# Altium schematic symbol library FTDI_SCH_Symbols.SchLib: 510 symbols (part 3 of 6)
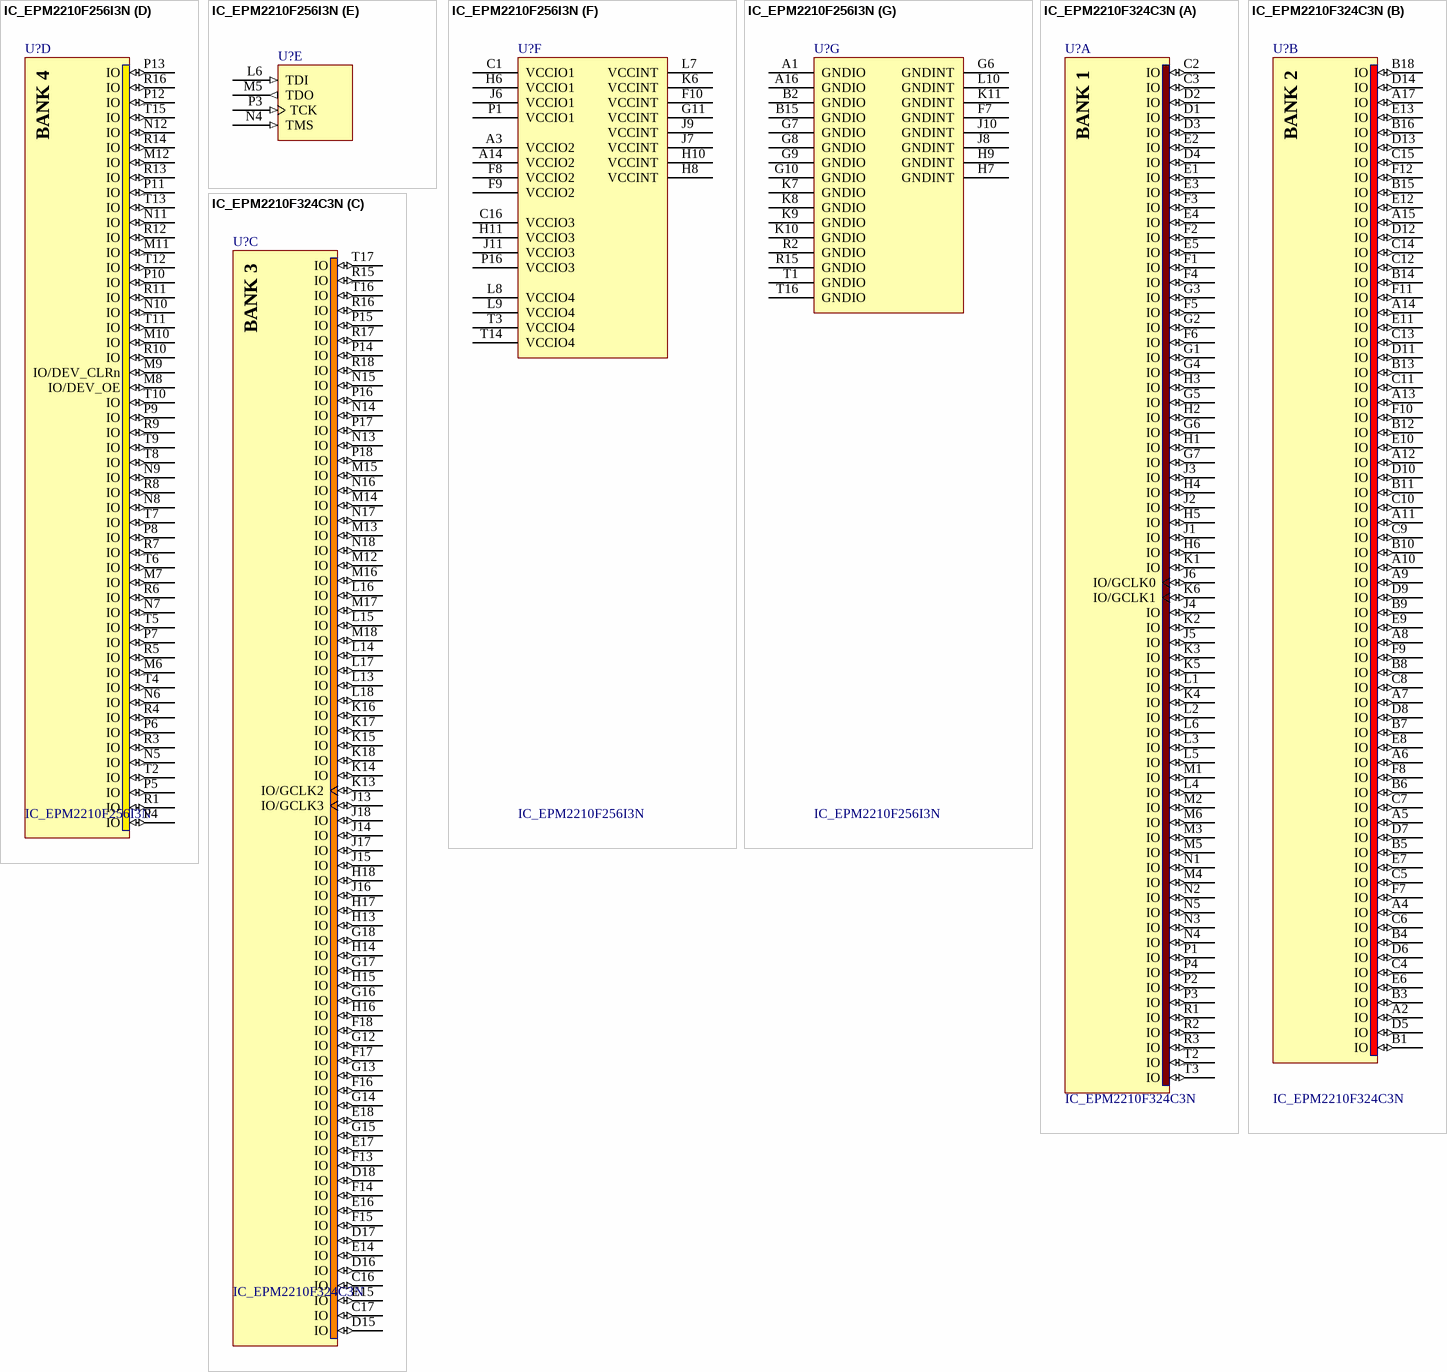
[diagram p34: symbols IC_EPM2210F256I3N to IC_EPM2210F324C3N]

## IC_EPM2210F256I3N
designator U?
MAX II 3.3/2.5V CPLD, 204 IOs, 2,210 Logic Elements, 256-Pin FineLine BGA, Industrial Temperature, Speed Grade 3, Pb-Free; Note: Each set of VCCIO pins can be connected to 3.3V, 2.5V, 1.8V, or 1.5V.; Note: All VCCINT pins must be connected to either 3.3V or 2.5V (but not a combination of both).
footprint FBGA256 (BGA, 256-Leads, Body 17x17mm, Pitch 1mm)
3D model EPM2210-FBGA256 (256-Ball FineLine Ball Grid Array (FBGA256) - Option 1)
part A pins: C2 IO (io), C3 IO (io), D1 IO (io), D2 IO (io), D3 IO (io), E1 IO (io), E2 IO (io), E3 IO (io), E4 IO (io), E5 IO (io), F1 IO (io), F2 IO (io), F3 IO (io), F4 IO (io), F5 IO (io), F6 IO (io), G1 IO (io), G2 IO (io), G3 IO (io), G4 IO (io), G5 IO (io), H1 IO (io), H2 IO (io), H3 IO (io), H4 IO (io), H5 IO/GCLK0 (io), J1 IO (io), J2 IO (io), J3 IO (io), J4 IO (io), J5 IO/GCLK1 (io), K1 IO (io), K2 IO (io), K3 IO (io), K4 IO (io), K5 IO (io), L1 IO (io), L2 IO (io), L3 IO (io), L4 IO (io), L5 IO (io), M1 IO (io), M2 IO (io), M3 IO (io), M4 IO (io), N1 IO (io), N2 IO (io), N3 IO (io), P2 IO (io)
part B pins: A2 IO (io), A4 IO (io), A5 IO (io), A6 IO (io), A7 IO (io), A8 IO (io), A9 IO (io), A10 IO (io), A11 IO (io), A12 IO (io), A13 IO (io), A15 IO (io), B1 IO (io), B3 IO (io), B4 IO (io), B5 IO (io), B6 IO (io), B7 IO (io), B8 IO (io), B9 IO (io), B10 IO (io), B11 IO (io), B12 IO (io), B13 IO (io), B14 IO (io), B16 IO (io), C4 IO (io), C5 IO (io), C6 IO (io), C7 IO (io), C8 IO (io), C9 IO (io), C10 IO (io), C11 IO (io), C12 IO (io), C13 IO (io), D4 IO (io), D5 IO (io), D6 IO (io), D7 IO (io), D8 IO (io), D9 IO (io), D10 IO (io), D11 IO (io), D12 IO (io), E6 IO (io), E7 IO (io), E8 IO (io), E9 IO (io), E10 IO (io), E11 IO (io)
part C pins: C14 IO (io), C15 IO (io), D13 IO (io), D14 IO (io), D15 IO (io), D16 IO (io), E12 IO (io), E13 IO (io), E14 IO (io), E15 IO (io), E16 IO (io), F11 IO (io), F12 IO (io), F13 IO (io), F14 IO (io), F15 IO (io), F16 IO (io), G12 IO (io), G13 IO (io), G14 IO (io), G15 IO (io), G16 IO (io), H12 IO/GCLK3 (io), H13 IO (io), H14 IO (io), H15 IO (io), H16 IO (io), J12 IO/GCLK2 (io), J13 IO (io), J14 IO (io), J15 IO (io), J16 IO (io), K12 IO (io), K13 IO (io), K14 IO (io), K15 IO (io), K16 IO (io), L11 IO (io), L12 IO (io), L13 IO (io), L14 IO (io), L15 IO (io), L16 IO (io), M13 IO (io), M14 IO (io), M15 IO (io), M16 IO (io), N13 IO (io), N14 IO (io), N15 IO (io), N16 IO (io), P14 IO (io), P15 IO (io)
part D pins: M6 IO (io), M7 IO (io), M8 IO/DEV_OE (io), M9 IO/DEV_CLRn (io), M10 IO (io), M11 IO (io), M12 IO (io), N5 IO (io), N6 IO (io), N7 IO (io), N8 IO (io), N9 IO (io), N10 IO (io), N11 IO (io), N12 IO (io), P4 IO (io), P5 IO (io), P6 IO (io), P7 IO (io), P8 IO (io), P9 IO (io), P10 IO (io), P11 IO (io), P12 IO (io), P13 IO (io), R1 IO (io), R3 IO (io), R4 IO (io), R5 IO (io), R6 IO (io), R7 IO (io), R8 IO (io), R9 IO (io), R10 IO (io), R11 IO (io), R12 IO (io), R13 IO (io), R14 IO (io), R16 IO (io), T2 IO (io), T4 IO (io), T5 IO (io), T6 IO (io), T7 IO (io), T8 IO (io), T9 IO (io), T10 IO (io), T11 IO (io), T12 IO (io), T13 IO (io), T15 IO (io)
part E pins: L6 TDI (in), M5 TDO (out), N4 TMS (in), P3 TCK (in)
part F pins: A3 VCCIO2 (power), A14 VCCIO2 (power), C1 VCCIO1 (power), C16 VCCIO3 (power), F8 VCCIO2 (power), F9 VCCIO2 (power), F10 VCCINT (power), G11 VCCINT (power), H6 VCCIO1 (power), H8 VCCINT (power), H10 VCCINT (power), H11 VCCIO3 (power), J6 VCCIO1 (power), J7 VCCINT (power), J9 VCCINT (power), J11 VCCIO3 (power), K6 VCCINT (power), L7 VCCINT (power), L8 VCCIO4 (power), L9 VCCIO4 (power), P1 VCCIO1 (power), P16 VCCIO3 (power), T3 VCCIO4 (power), T14 VCCIO4 (power)
part G pins: A1 GNDIO (power), A16 GNDIO (power), B2 GNDIO (power), B15 GNDIO (power), F7 GNDINT (power), G6 GNDINT (power), G7 GNDIO (power), G8 GNDIO (power), G9 GNDIO (power), G10 GNDIO (power), H7 GNDINT (power), H9 GNDINT (power), J8 GNDINT (power), J10 GNDINT (power), K7 GNDIO (power), K8 GNDIO (power), K9 GNDIO (power), K10 GNDIO (power), K11 GNDINT (power), L10 GNDINT (power), R2 GNDIO (power), R15 GNDIO (power), T1 GNDIO (power), T16 GNDIO (power)

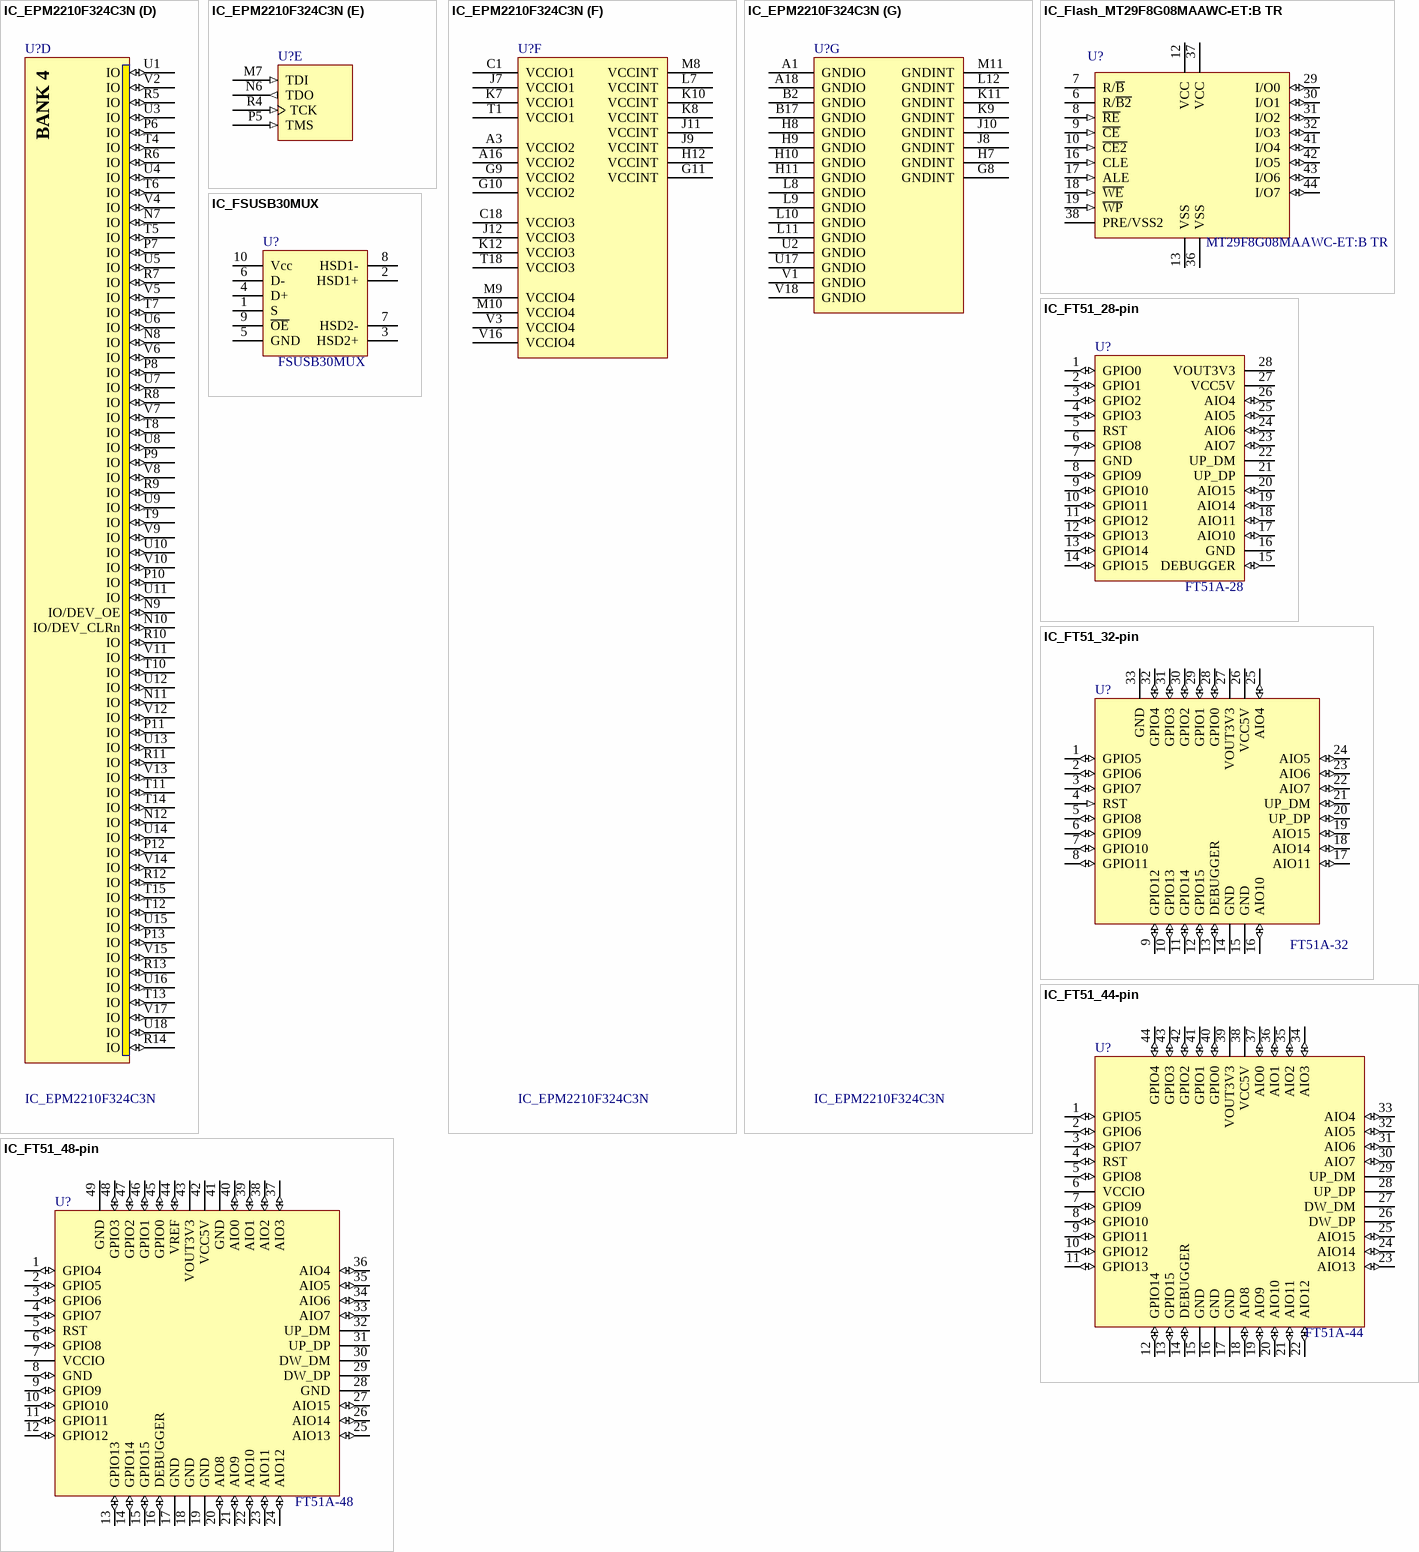
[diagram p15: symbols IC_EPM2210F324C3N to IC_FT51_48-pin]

## IC_EPM2210F324C3N
designator U?
MAX II 3.3/2.5V CPLD, 272 IOs, 2,210 Logic Elements, 324-Pin FineLine BGA, Commercial Temperature, Speed Grade 3, Pb-Free; Note: Each set of VCCIO pins can be connected to 3.3V, 2.5V, 1.8V, or 1.5V.; Note: All VCCINT pins must be connected to either 3.3V or 2.5V (but not a combination of both).
footprint FBGA324 (BGA, 324-Leads, Body 19x19mm, Pitch 1mm)
3D model EPM2210-FBGA324 (324-Ball FineLine Ball Grid Array (FBGA324))
part A pins: C2 IO (io), C3 IO (io), D1 IO (io), D2 IO (io), D3 IO (io), D4 IO (io), E1 IO (io), E2 IO (io), E3 IO (io), E4 IO (io), E5 IO (io), F1 IO (io), F2 IO (io), F3 IO (io), F4 IO (io), F5 IO (io), F6 IO (io), G1 IO (io), G2 IO (io), G3 IO (io), G4 IO (io), G5 IO (io), G6 IO (io), G7 IO (io), H1 IO (io), H2 IO (io), H3 IO (io), H4 IO (io), H5 IO (io), H6 IO (io), J1 IO (io), J2 IO (io), J3 IO (io), J4 IO (io), J5 IO (io), J6 IO/GCLK0 (io), K1 IO (io), K2 IO (io), K3 IO (io), K4 IO (io), K5 IO (io), K6 IO/GCLK1 (io), L1 IO (io), L2 IO (io), L3 IO (io), L4 IO (io), L5 IO (io), L6 IO (io), M1 IO (io), M2 IO (io), M3 IO (io), M4 IO (io), M5 IO (io), M6 IO (io), N1 IO (io), N2 IO (io), N3 IO (io), N4 IO (io), N5 IO (io), P1 IO (io), P2 IO (io), P3 IO (io), P4 IO (io), R1 IO (io), R2 IO (io), R3 IO (io), T2 IO (io), T3 IO (io)
part B pins: A2 IO (io), A4 IO (io), A5 IO (io), A6 IO (io), A7 IO (io), A8 IO (io), A9 IO (io), A10 IO (io), A11 IO (io), A12 IO (io), A13 IO (io), A14 IO (io), A15 IO (io), A17 IO (io), B1 IO (io), B3 IO (io), B4 IO (io), B5 IO (io), B6 IO (io), B7 IO (io), B8 IO (io), B9 IO (io), B10 IO (io), B11 IO (io), B12 IO (io), B13 IO (io), B14 IO (io), B15 IO (io), B16 IO (io), B18 IO (io), C4 IO (io), C5 IO (io), C6 IO (io), C7 IO (io), C8 IO (io), C9 IO (io), C10 IO (io), C11 IO (io), C12 IO (io), C13 IO (io), C14 IO (io), C15 IO (io), D5 IO (io), D6 IO (io), D7 IO (io), D8 IO (io), D9 IO (io), D10 IO (io), D11 IO (io), D12 IO (io), D13 IO (io), D14 IO (io), E6 IO (io), E7 IO (io), E8 IO (io), E9 IO (io), E10 IO (io), E11 IO (io), E12 IO (io), E13 IO (io), F7 IO (io), F8 IO (io), F9 IO (io), F10 IO (io), F11 IO (io), F12 IO (io)
part C pins: C16 IO (io), C17 IO (io), D15 IO (io), D16 IO (io), D17 IO (io), D18 IO (io), E14 IO (io), E15 IO (io), E16 IO (io), E17 IO (io), E18 IO (io), F13 IO (io), F14 IO (io), F15 IO (io), F16 IO (io), F17 IO (io), F18 IO (io), G12 IO (io), G13 IO (io), G14 IO (io), G15 IO (io), G16 IO (io), G17 IO (io), G18 IO (io), H13 IO (io), H14 IO (io), H15 IO (io), H16 IO (io), H17 IO (io), H18 IO (io), J13 IO/GCLK3 (io), J14 IO (io), J15 IO (io), J16 IO (io), J17 IO (io), J18 IO (io), K13 IO/GCLK2 (io), K14 IO (io), K15 IO (io), K16 IO (io), K17 IO (io), K18 IO (io), L13 IO (io), L14 IO (io), L15 IO (io), L16 IO (io), L17 IO (io), L18 IO (io), M12 IO (io), M13 IO (io), M14 IO (io), M15 IO (io), M16 IO (io), M17 IO (io), M18 IO (io), N13 IO (io), N14 IO (io), N15 IO (io), N16 IO (io), N17 IO (io), N18 IO (io), P14 IO (io), P15 IO (io), P16 IO (io), P17 IO (io), P18 IO (io), R15 IO (io), R16 IO (io), R17 IO (io), R18 IO (io), T16 IO (io), T17 IO (io)
part D pins: N7 IO (io), N8 IO (io), N9 IO/DEV_OE (io), N10 IO/DEV_CLRn (io), N11 IO (io), N12 IO (io), P6 IO (io), P7 IO (io), P8 IO (io), P9 IO (io), P10 IO (io), P11 IO (io), P12 IO (io), P13 IO (io), R5 IO (io), R6 IO (io), R7 IO (io), R8 IO (io), R9 IO (io), R10 IO (io), R11 IO (io), R12 IO (io), R13 IO (io), R14 IO (io), T4 IO (io), T5 IO (io), T6 IO (io), T7 IO (io), T8 IO (io), T9 IO (io), T10 IO (io), T11 IO (io), T12 IO (io), T13 IO (io), T14 IO (io), T15 IO (io), U1 IO (io), U3 IO (io), U4 IO (io), U5 IO (io), U6 IO (io), U7 IO (io), U8 IO (io), U9 IO (io), U10 IO (io), U11 IO (io), U12 IO (io), U13 IO (io), U14 IO (io), U15 IO (io), U16 IO (io), U18 IO (io), V2 IO (io), V4 IO (io), V5 IO (io), V6 IO (io), V7 IO (io), V8 IO (io), V9 IO (io), V10 IO (io), V11 IO (io), V12 IO (io), V13 IO (io), V14 IO (io), V15 IO (io), V17 IO (io)
part E pins: M7 TDI (in), N6 TDO (out), P5 TMS (in), R4 TCK (in)
part F pins: A3 VCCIO2 (power), A16 VCCIO2 (power), C1 VCCIO1 (power), C18 VCCIO3 (power), G9 VCCIO2 (power), G10 VCCIO2 (power), G11 VCCINT (power), H12 VCCINT (power), J7 VCCIO1 (power), J9 VCCINT (power), J11 VCCINT (power), J12 VCCIO3 (power), K7 VCCIO1 (power), K8 VCCINT (power), K10 VCCINT (power), K12 VCCIO3 (power), L7 VCCINT (power), M8 VCCINT (power), M9 VCCIO4 (power), M10 VCCIO4 (power), T1 VCCIO1 (power), T18 VCCIO3 (power), V3 VCCIO4 (power), V16 VCCIO4 (power)
part G pins: A1 GNDIO (power), A18 GNDIO (power), B2 GNDIO (power), B17 GNDIO (power), G8 GNDINT (power), H7 GNDINT (power), H8 GNDIO (power), H9 GNDIO (power), H10 GNDIO (power), H11 GNDIO (power), J8 GNDINT (power), J10 GNDINT (power), K9 GNDINT (power), K11 GNDINT (power), L8 GNDIO (power), L9 GNDIO (power), L10 GNDIO (power), L11 GNDIO (power), L12 GNDINT (power), M11 GNDINT (power), U2 GNDIO (power), U17 GNDIO (power), V1 GNDIO (power), V18 GNDIO (power)

## IC_Flash_MT29F8G08MAAWC-ET:B TR
designator U?, comment MT29F8G08MAAWC-ET:B TR
8Gb: x8 Multiplexed NAND Flash Memory
footprint TSOP_Type1_50P2000X120-48N (TSOP Type 1, 48-Leads, Body 12.1x18.5mm (max), Pitch 0.50mm, IPC Medium Density)
pins: 1 NC hidden, 2 NC hidden, 3 NC hidden, 4 NC hidden, 5 NC hidden, 6 R/~{B2} (oc), 7 R/~{B} (oc), 8 ~{RE} (in), 9 ~{CE} (in), 10 ~{CE2} (in), 11 NC hidden, 12 VCC (power), 13 VSS (power), 14 NC hidden, 15 NC hidden, 16 CLE (in), 17 ALE (in), 18 ~{WE} (in), 19 ~{WP} (in), 20 DNU hidden, 21 DNU hidden, 22 DNU hidden, 23 NC hidden, 24 NC hidden, 25 NC hidden, 26 NC hidden, 27 NC hidden, 28 NC hidden, 29 I/O0 (io), 30 I/O1 (io), 31 I/O2 (io), 32 I/O3 (io), 33 NC hidden, 34 NC hidden, 35 NC hidden, 36 VSS (power), 37 VCC (power), 38 PRE/VSS2 (power), 39 NC hidden, 40 NC hidden, 41 I/O4 (io), 42 I/O5 (io), 43 I/O6 (io), 44 I/O7 (io), 45 NC hidden, 46 NC hidden, 47 NC hidden, 48 NC hidden

## IC_FSUSB30MUX
designator U?, comment FSUSB30MUX
Low Power, Two Port, High Speed USB2.0 Switch
footprint MSOP50P490X120-10N (MSOP, 10-Leads, Body 3.1x3.1mm (max), Pitch 0.50mm, IPC Medium Density)
pins: 1 S, 2 HSD1+, 3 HSD2+, 4 D+, 5 GND, 6 D-, 7 HSD2-, 8 HSD1-, 9 ~{OE}, 10 Vcc

## IC_FT51_28-pin
designator U?, comment FT51A-28
Preliminary symbol - DO NOT USE FOR COMERCIAL DESIGNS
pins: 1 GPIO0 (io), 2 GPIO1 (io), 3 GPIO2 (io), 4 GPIO3 (io), 5 RST (power), 6 GPIO8 (io), 7 GND (power), 8 GPIO9 (io), 9 GPIO10 (io), 10 GPIO11 (io), 11 GPIO12 (io), 12 GPIO13 (io), 13 GPIO14 (io), 14 GPIO15 (io), 15 DEBUGGER (io), 16 GND (power), 17 AIO10 (io), 18 AIO11 (io), 19 AIO14 (io), 20 AIO15 (io), 21 UP_DP, 22 UP_DM, 23 AIO7 (io), 24 AIO6 (io), 25 AIO5 (io), 26 AIO4 (io), 27 VCC5V (power), 28 VOUT3V3 (power)

## IC_FT51_32-pin
designator U?, comment FT51A-32
FT51A 32 pin QFN
footprint QFN50P598X598X75-32N (QFN, 32-Leads, Body 6.0x6.0mm (max), Pitch 0.50mm, IPC Medium Density)
pins: 1 GPIO5 (io), 2 GPIO6 (io), 3 GPIO7 (io), 4 RST (in), 5 GPIO8 (io), 6 GPIO9 (io), 7 GPIO10 (io), 8 GPIO11 (io), 9 GPIO12 (io), 10 GPIO13 (io), 11 GPIO14 (io), 12 GPIO15 (io), 13 DEBUGGER (io), 14 GND (power), 15 GND (power), 16 AIO10 (io), 17 AIO11 (io), 18 AIO14 (io), 19 AIO15 (io), 20 UP_DP (io), 21 UP_DM (io), 22 AIO7 (io), 23 AIO6 (io), 24 AIO5 (io), 25 AIO4 (io), 26 VCC5V (power), 27 VOUT3V3 (power), 28 GPIO0 (io), 29 GPIO1 (io), 30 GPIO2 (io), 31 GPIO3 (io), 32 GPIO4 (io), 33 GND

## IC_FT51_44-pin
designator U?, comment FT51A-44
Preliminary symbol - DO NOT USE FOR COMERCIAL DESIGNS
pins: 1 GPIO5 (io), 2 GPIO6 (io), 3 GPIO7 (io), 4 RST (io), 5 GPIO8 (io), 6 VCCIO (power), 7 GPIO9 (io), 8 GPIO10 (io), 9 GPIO11 (io), 10 GPIO12 (io), 11 GPIO13 (io), 12 GPIO14 (io), 13 GPIO15 (io), 14 DEBUGGER (io), 15 GND (power), 16 GND (power), 17 GND (power), 18 AIO8 (io), 19 AIO9 (io), 20 AIO10 (io), 21 AIO11 (io), 22 AIO12 (io), 23 AIO13 (io), 24 AIO14 (io), 25 AIO15 (io), 26 DW_DP, 27 DW_DM, 28 UP_DP, 29 UP_DM, 30 AIO7 (io), 31 AIO6 (io), 32 AIO5 (io), 33 AIO4 (io), 34 AIO3 (io), 35 AIO2 (io), 36 AIO1 (io), 37 AIO0 (io), 38 VCC5V (power), 39 VOUT3V3 (power), 40 GPIO0 (io), 41 GPIO1 (io), 42 GPIO2 (io), 43 GPIO3 (io), 44 GPIO4 (io)

## IC_FT51_48-pin
designator U?, comment FT51A-48
Preliminary symbol - DO NOT USE FOR COMERCIAL DESIGNS
pins: 1 GPIO4 (io), 2 GPIO5 (io), 3 GPIO6 (io), 4 GPIO7 (io), 5 RST (io), 6 GPIO8 (io), 7 VCCIO (power), 8 GND (io), 9 GPIO9 (io), 10 GPIO10 (io), 11 GPIO11 (io), 12 GPIO12 (io), 13 GPIO13 (io), 14 GPIO14 (io), 15 GPIO15 (io), 16 DEBUGGER (io), 17 GND (power), 18 GND (power), 19 GND (power), 20 AIO8 (io), 21 AIO9 (io), 22 AIO10 (io), 23 AIO11 (io), 24 AIO12 (io), 25 AIO13 (io), 26 AIO14 (io), 27 AIO15 (io), 28 GND (power), 29 DW_DP, 30 DW_DM, 31 UP_DP, 32 UP_DM, 33 AIO7 (io), 34 AIO6 (io), 35 AIO5 (io), 36 AIO4 (io), 37 AIO3 (io), 38 AIO2 (io), 39 AIO1 (io), 40 AIO0 (io), 41 GND (power), 42 VCC5V (power), 43 VOUT3V3 (power), 44 VREF (io), 45 GPIO0 (io), 46 GPIO1 (io), 47 GPIO2 (io), 48 GPIO3 (io), 49 GND (power)

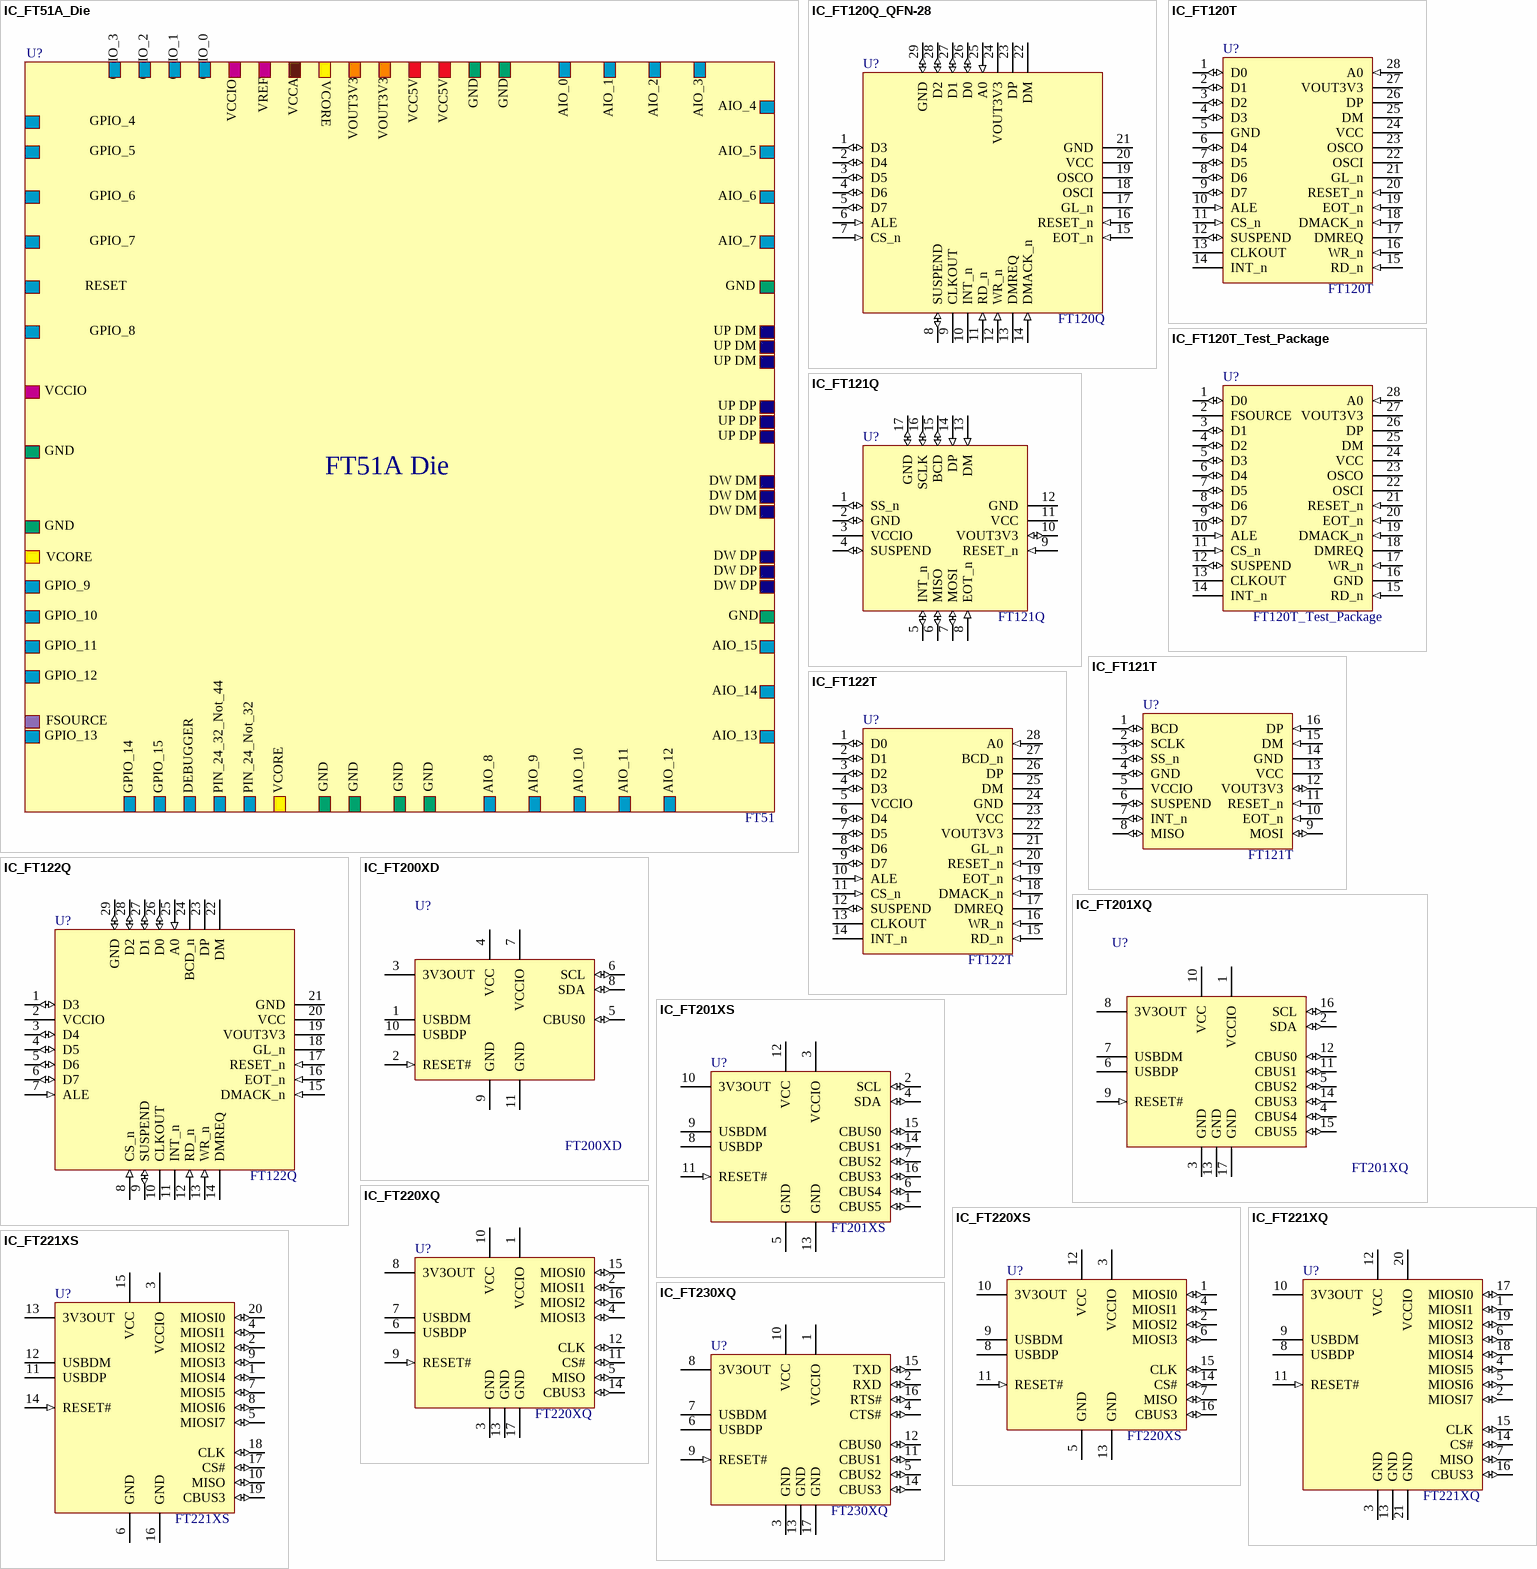
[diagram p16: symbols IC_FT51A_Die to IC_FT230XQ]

## IC_FT51A_Die
designator U?, comment FT51
Not for customer designs

## IC_FT120Q_QFN-28
designator U?, comment FT120Q
footprint QFN40P400X400X90-28N (QFN, 28-Leads, Body 4x4mm (max), Pitch 0.40mm, IPC Medium Density)
pins: 1 D3 (io), 2 D4 (io), 3 D5 (io), 4 D6 (io), 5 D7 (io), 6 ALE (in), 7 CS_n (in), 8 SUSPEND (io), 9 CLKOUT, 10 INT_n (oc), 11 RD_n (in), 12 WR_n (in), 13 DMREQ (oc), 14 DMACK_n (in), 15 EOT_n (in), 16 RESET_n (in), 17 GL_n (oc), 18 OSCI, 19 OSCO, 20 VCC (power), 21 GND (power), 22 DM, 23 DP, 24 VOUT3V3 (power), 25 A0 (in), 26 D0 (io), 27 D1 (io), 28 D2 (io), 29 GND (io)

## IC_FT120T
designator U?, comment FT120T
footprint TSSOP65P640X120-28N (TSSOP, 28-Leads, Body 9.8x4.4mm (max), Pitch 0.65mm, IPC Medium Density)
pins: 1 D0 (io), 2 D1 (io), 3 D2 (io), 4 D3 (io), 5 GND (power), 6 D4 (io), 7 D5 (io), 8 D6 (io), 9 D7 (io), 10 ALE (in), 11 CS_n (in), 12 SUSPEND (io), 13 CLKOUT, 14 INT_n (oc), 15 RD_n (in), 16 WR_n (in), 17 DMREQ (oc), 18 DMACK_n (in), 19 EOT_n (in), 20 RESET_n (in), 21 GL_n (oc), 22 OSCI, 23 OSCO, 24 VCC (power), 25 DM, 26 DP, 27 VOUT3V3 (power), 28 A0 (in)

## IC_FT120T_Test_Package
designator U?, comment FT120T_Test_Package
footprint TSSOP65P640X120-28N (TSSOP, 28-Leads, Body 9.8x4.4mm (max), Pitch 0.65mm, IPC Medium Density)
pins: 1 D0 (io), 2 FSOURCE (power), 3 D1 (io), 4 D2 (io), 5 D3 (io), 6 D4 (io), 7 D5 (io), 8 D6 (io), 9 D7 (io), 10 ALE (in), 11 CS_n (in), 12 SUSPEND (io), 13 CLKOUT, 14 INT_n (oc), 15 RD_n (in), 16 GND (oc), 17 WR_n (in), 18 DMREQ (oc), 19 DMACK_n (in), 20 EOT_n (in), 21 RESET_n (in), 22 OSCI, 23 OSCO, 24 VCC (power), 25 DM, 26 DP, 27 VOUT3V3 (power), 28 A0 (in)

## IC_FT121Q
designator U?, comment FT121Q
footprint QFN50P300X300X90-16N (QFN, 16-Leads, Body 3.1x3.1mm (max), Pitch 0.50mm, IPC Medium Density)
pins: 1 SS_n (io), 2 GND (io), 3 VCCIO (power), 4 SUSPEND (io), 5 INT_n (io), 6 MISO (io), 7 MOSI (io), 8 EOT_n (in), 9 RESET_n (in), 10 VOUT3V3 (io), 11 VCC, 12 GND (oc), 13 DM (in), 14 DP (in), 15 BCD (io), 16 SCLK (io), 17 GND (io)

## IC_FT121T
designator U?, comment FT121T
footprint TSSOP65P640X120-16N (TSOP, 16-Leads, Body 5.1x4.5mm (max), Pitch 0.65mm, IPC Medium Density)
pins: 1 BCD (io), 2 SCLK (io), 3 SS_n (io), 4 GND (io), 5 VCCIO (power), 6 SUSPEND (io), 7 INT_n (io), 8 MISO (io), 9 MOSI (io), 10 EOT_n (in), 11 RESET_n (in), 12 VOUT3V3 (io), 13 VCC, 14 GND (oc), 15 DM (in), 16 DP (in)

## IC_FT122Q
designator U?, comment FT122Q
footprint QFN40P400X400X90-28N (QFN, 28-Leads, Body 4x4mm (max), Pitch 0.40mm, IPC Medium Density)
pins: 1 D3 (io), 2 VCCIO (power), 3 D4 (io), 4 D5 (io), 5 D6 (io), 6 D7 (io), 7 ALE (in), 8 CS_n (in), 9 SUSPEND (io), 10 CLKOUT, 11 INT_n (oc), 12 RD_n (in), 13 WR_n (in), 14 DMREQ (oc), 15 DMACK_n (in), 16 EOT_n (in), 17 RESET_n (in), 18 GL_n (oc), 19 VOUT3V3, 20 VCC, 21 GND (power), 22 DM, 23 DP, 24 BCD_n (power), 25 A0 (in), 26 D0 (io), 27 D1 (io), 28 D2 (io), 29 GND (io)

## IC_FT122T
designator U?, comment FT122T
footprint TSSOP65P640X120-28N (TSSOP, 28-Leads, Body 9.8x4.4mm (max), Pitch 0.65mm, IPC Medium Density)
pins: 1 D0 (io), 2 D1 (io), 3 D2 (io), 4 D3 (io), 5 VCCIO (power), 6 D4 (io), 7 D5 (io), 8 D6 (io), 9 D7 (io), 10 ALE (in), 11 CS_n (in), 12 SUSPEND (io), 13 CLKOUT, 14 INT_n (oc), 15 RD_n (in), 16 WR_n (in), 17 DMREQ (oc), 18 DMACK_n (in), 19 EOT_n (in), 20 RESET_n (in), 21 GL_n (oc), 22 VOUT3V3, 23 VCC, 24 GND (power), 25 DM, 26 DP, 27 BCD_n (power), 28 A0 (in)

## IC_FT200XD
designator U?, comment FT200XD
FT200XD DFN-10
pins: 1 USBDM, 2 RESET# (in), 3 3V3OUT (power), 4 VCC (power), 5 CBUS0 (io), 6 SCL (io), 7 VCCIO (power), 8 SDA (io), 9 GND (power), 10 USBDP, 11 GND (power)

## IC_FT201XQ
designator U?, comment FT201XQ
FT201XQ-QFN-16
footprint VQFN65P400X400X90-16N (VQFN, 16-Leads, Body 4.0x4.0mm (max), Pitch 0.65mm, IPC Medium Density)
pins: 1 VCCIO (power), 2 SDA (io), 3 GND (power), 4 CBUS4 (io), 5 CBUS2 (io), 6 USBDP, 7 USBDM, 8 3V3OUT (power), 9 RESET# (in), 10 VCC (power), 11 CBUS1 (io), 12 CBUS0 (io), 13 GND (power), 14 CBUS3 (io), 15 CBUS5 (io), 16 SCL (io), 17 GND (power)

## IC_FT201XS
designator U?, comment FT201XS
FT201XS-SSOP-16
footprint SSOP635P600X175-16N (SSOP, 16-Leads, Body 4.9x3.9mm (max), Pitch 0.635mm, IPC Medium Density)
pins: 1 CBUS5 (io), 2 SCL (io), 3 VCCIO (power), 4 SDA (io), 5 GND (power), 6 CBUS4 (io), 7 CBUS2 (io), 8 USBDP, 9 USBDM, 10 3V3OUT (power), 11 RESET# (in), 12 VCC (power), 13 GND (power), 14 CBUS1 (io), 15 CBUS0 (io), 16 CBUS3 (io)

## IC_FT220XQ
designator U?, comment FT220XQ
FT220XQ-QFN-16
footprint VQFN65P400X400X90-16N (VQFN, 16-Leads, Body 4.0x4.0mm (max), Pitch 0.65mm, IPC Medium Density)
pins: 1 VCCIO (power), 2 MIOSI1 (io), 3 GND (power), 4 MIOSI3 (io), 5 MISO (io), 6 USBDP, 7 USBDM, 8 3V3OUT (power), 9 RESET# (in), 10 VCC (power), 11 CS# (io), 12 CLK (io), 13 GND (power), 14 CBUS3 (io), 15 MIOSI0 (io), 16 MIOSI2 (io), 17 GND (power)

## IC_FT220XS
designator U?, comment FT220XS
FT220XS-SSOP-16
footprint SSOP635P600X175-16N (SSOP, 16-Leads, Body 4.9x3.9mm (max), Pitch 0.635mm, IPC Medium Density)
pins: 1 MIOSI0 (io), 2 MIOSI2 (io), 3 VCCIO (power), 4 MIOSI1 (io), 5 GND (power), 6 MIOSI3 (io), 7 MISO (io), 8 USBDP, 9 USBDM, 10 3V3OUT (power), 11 RESET# (in), 12 VCC (power), 13 GND (power), 14 CS# (io), 15 CLK (io), 16 CBUS3 (io)

## IC_FT221XQ
designator U?, comment FT221XQ
FT221XQ-QFN-20
footprint VQFN50P400X400X90-20N (VQFN, 20-Leads, Body 4.0x4.0mm (max), Pitch 0.50mm, IPC Medium Density)
pins: 1 MIOSI1 (io), 2 MIOSI7 (io), 3 GND (power), 4 MIOSI5 (io), 5 MIOSI6 (io), 6 MIOSI3 (io), 7 MISO (io), 8 USBDP, 9 USBDM, 10 3V3OUT (power), 11 RESET# (in), 12 VCC (power), 13 GND (power), 14 CS# (io), 15 CLK (io), 16 CBUS3 (io), 17 MIOSI0 (io), 18 MIOSI4 (io), 19 MIOSI2 (io), 20 VCCIO (power), 21 GND (power)

## IC_FT221XS
designator U?, comment FT221XS
FT221XS-SSOP-20
footprint SSOP635P600X175-20N (SSOP, 20-Leads, Body 8.7x4.0mm (max), Pitch 0.635mm, IPC Medium Density)
pins: 1 MIOSI4 (io), 2 MIOSI2 (io), 3 VCCIO (power), 4 MIOSI1 (io), 5 MIOSI7 (io), 6 GND (power), 7 MIOSI5 (io), 8 MIOSI6 (io), 9 MIOSI3 (io), 10 MISO (io), 11 USBDP, 12 USBDM, 13 3V3OUT (power), 14 RESET# (in), 15 VCC (power), 16 GND (power), 17 CS# (io), 18 CLK (io), 19 CBUS3 (io), 20 MIOSI0 (io)

## IC_FT230XQ
designator U?, comment FT230XQ
FT230XQ-QFN-16
footprint VQFN65P400X400X90-16N (VQFN, 16-Leads, Body 4.0x4.0mm (max), Pitch 0.65mm, IPC Medium Density)
pins: 1 VCCIO (power), 2 RXD (io), 3 GND (power), 4 CTS# (io), 5 CBUS2 (io), 6 USBDP, 7 USBDM, 8 3V3OUT (power), 9 RESET# (in), 10 VCC (power), 11 CBUS1 (io), 12 CBUS0 (io), 13 GND (power), 14 CBUS3 (io), 15 TXD (io), 16 RTS# (io), 17 GND (power)

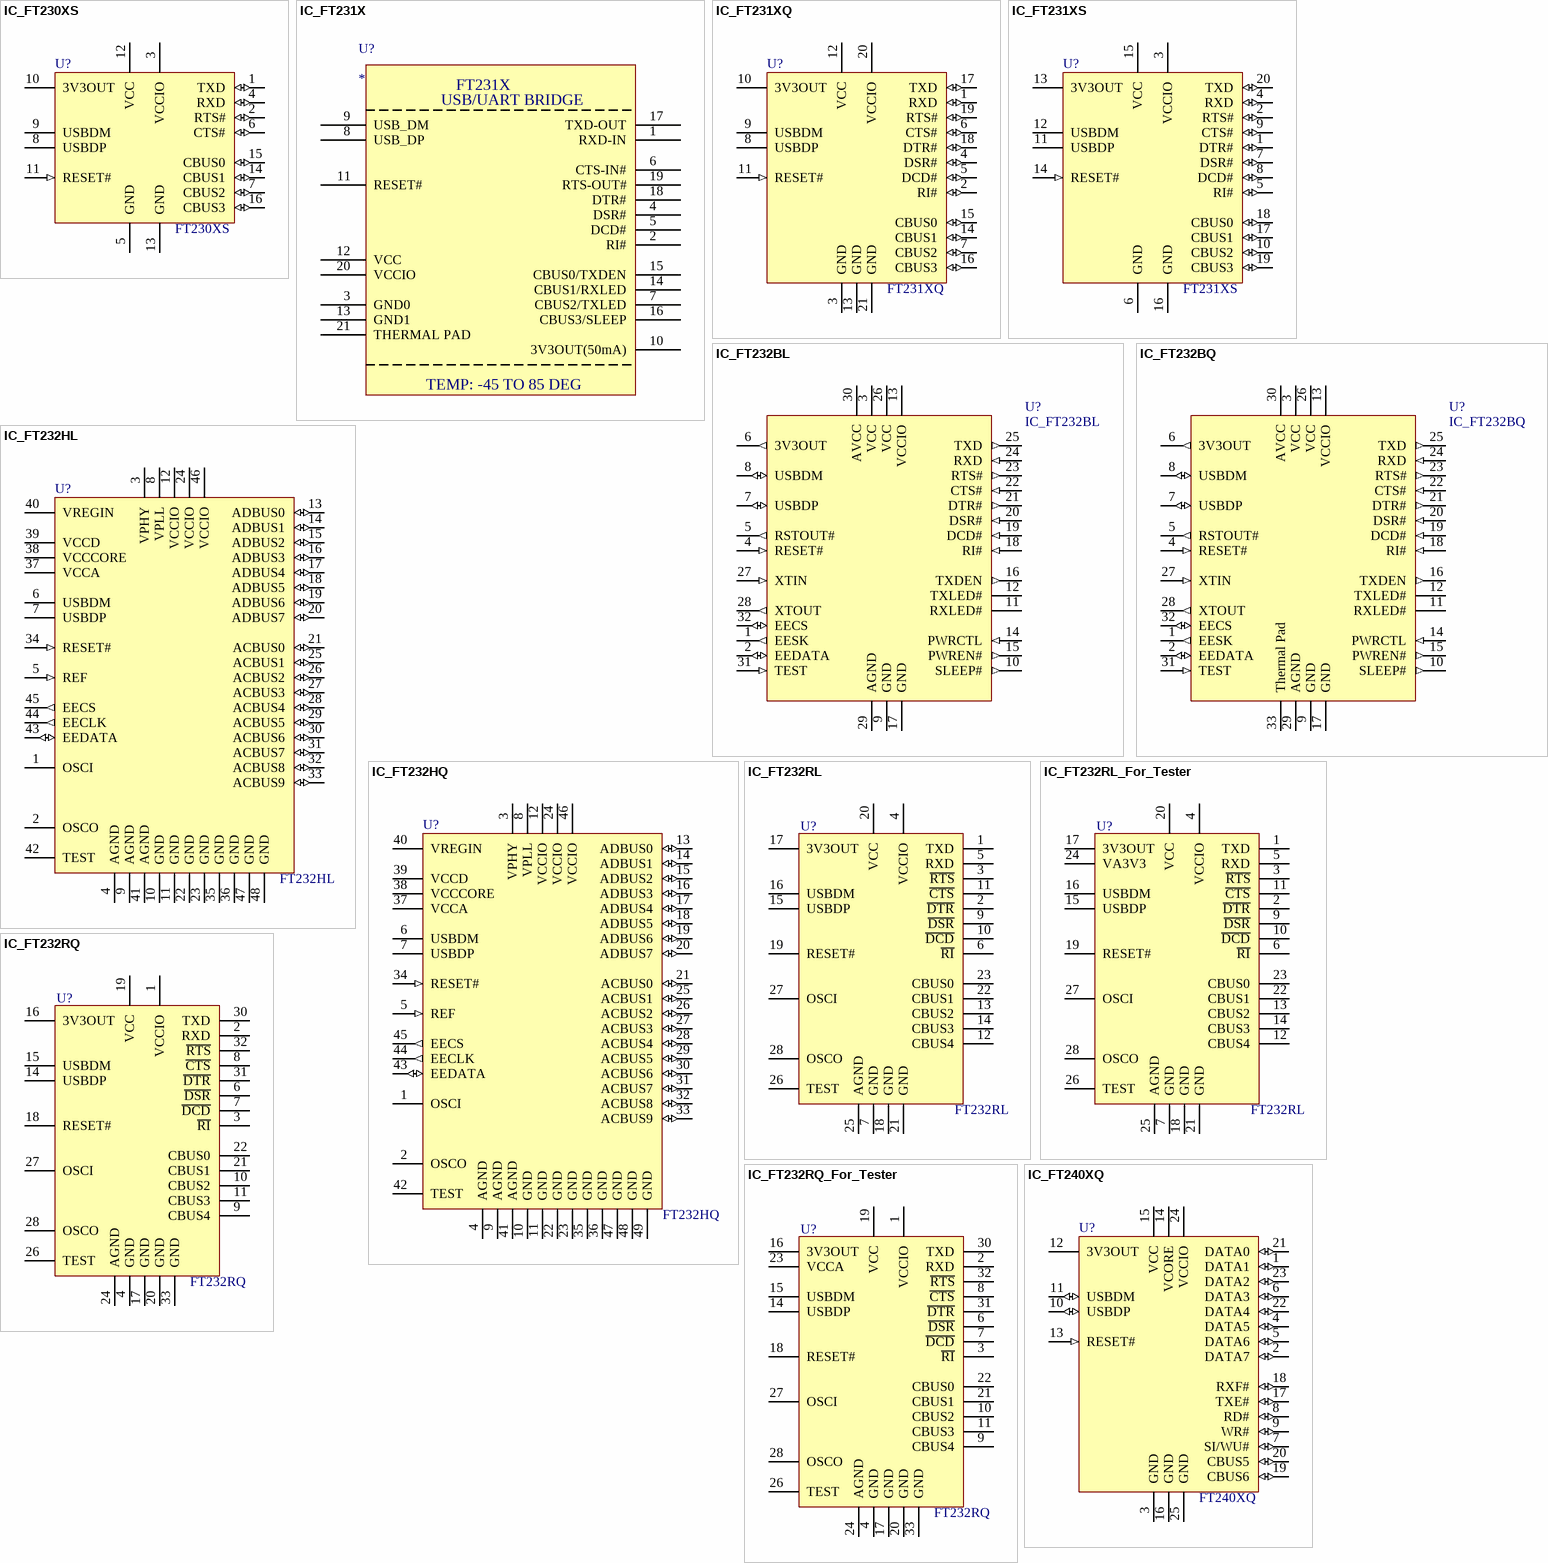
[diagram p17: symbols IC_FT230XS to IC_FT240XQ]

## IC_FT230XS
designator U?, comment FT230XS
FT230XS-SSOP-16
footprint SSOP635P600X175-16N (SSOP, 16-Leads, Body 4.9x3.9mm (max), Pitch 0.635mm, IPC Medium Density)
pins: 1 TXD (io), 2 RTS# (io), 3 VCCIO (power), 4 RXD (io), 5 GND (power), 6 CTS# (io), 7 CBUS2 (io), 8 USBDP, 9 USBDM, 10 3V3OUT (power), 11 RESET# (in), 12 VCC (power), 13 GND (power), 14 CBUS1 (io), 15 CBUS0 (io), 16 CBUS3 (io)

## IC_FT231X
designator U?
pins: 1 RXD-IN, 2 RI#, 3 GND0, 4 DSR#, 5 DCD#, 6 CTS-IN#, 7 CBUS2/TXLED, 8 USB_DP, 9 USB_DM, 10 3V3OUT(50mA), 11 RESET#, 12 VCC, 13 GND1, 14 CBUS1/RXLED, 15 CBUS0/TXDEN, 16 CBUS3/SLEEP, 17 TXD-OUT, 18 DTR#, 19 RTS-OUT#, 20 VCCIO, 21 THERMAL PAD

## IC_FT231XQ
designator U?, comment FT231XQ
FT231XQ-QFN-20
footprint VQFN50P400X400X90-20N (VQFN, 20-Leads, Body 4.0x4.0mm (max), Pitch 0.50mm, IPC Medium Density)
pins: 1 RXD (io), 2 RI# (io), 3 GND (power), 4 DSR# (io), 5 DCD# (io), 6 CTS# (io), 7 CBUS2 (io), 8 USBDP, 9 USBDM, 10 3V3OUT (power), 11 RESET# (in), 12 VCC (power), 13 GND (power), 14 CBUS1 (io), 15 CBUS0 (io), 16 CBUS3 (io), 17 TXD (io), 18 DTR# (io), 19 RTS# (io), 20 VCCIO (power), 21 GND (power)

## IC_FT231XS
designator U?, comment FT231XS
FT231XS-SSOP-20
footprint SSOP635P600X175-20N (SSOP, 20-Leads, Body 8.7x4.0mm (max), Pitch 0.635mm, IPC Medium Density)
pins: 1 DTR# (io), 2 RTS# (io), 3 VCCIO (power), 4 RXD (io), 5 RI# (io), 6 GND (power), 7 DSR# (io), 8 DCD# (io), 9 CTS# (io), 10 CBUS2 (io), 11 USBDP, 12 USBDM, 13 3V3OUT (power), 14 RESET# (in), 15 VCC (power), 16 GND (power), 17 CBUS1 (io), 18 CBUS0 (io), 19 CBUS3 (io), 20 TXD (io)

## IC_FT232BL
designator U?
Single chip USB to UART interface; LQFP-32, Pb-Free; Manufacturer: Future Technology Devices International Ltd. (FTDI)
footprint LQFP-32_N (32-Pin Thin Quad Flat Pack 0.8 mm Pitch, IPC Medium Density)
footprint LQFP-32_L (32-Pin Thin Quad Flat Pack 0.8 mm Pitch, IPC High Density)
footprint LQFP-32_M (32-Pin Thin Quad Flat Pack 0.8 mm Pitch, IPC Low Density)
pins: 1 EESK (out), 2 EEDATA (io), 3 VCC (power), 4 RESET# (in), 5 RSTOUT# (out), 6 3V3OUT (out), 7 USBDP (io), 8 USBDM (io), 9 GND (power), 10 SLEEP# (out), 11 RXLED# (oc), 12 TXLED# (oc), 13 VCCIO (power), 14 PWRCTL (in), 15 PWREN# (out), 16 TXDEN (out), 17 GND (power), 18 RI# (in), 19 DCD# (in), 20 DSR# (in), 21 DTR# (out), 22 CTS# (in), 23 RTS# (out), 24 RXD (in), 25 TXD (out), 26 VCC (power), 27 XTIN (in), 28 XTOUT (out), 29 AGND (power), 30 AVCC (power), 31 TEST (in), 32 EECS (io)

## IC_FT232BQ
designator U?
Single chip USB to UART interface; QFN32, Pb-Free; Manufacturer: Future Technology Devices International Ltd. (FTDI)
footprint VQFN50P500X500-X90-32N (QFN, 32-Leads, Body 5.1x5.1mm (max), Pitch 0.50mm, IPC Medium Density)
pins: 1 EESK (out), 2 EEDATA (io), 3 VCC (power), 4 RESET# (in), 5 RSTOUT# (out), 6 3V3OUT (out), 7 USBDP (io), 8 USBDM (io), 9 GND (power), 10 SLEEP# (out), 11 RXLED# (oc), 12 TXLED# (oc), 13 VCCIO (power), 14 PWRCTL (in), 15 PWREN# (out), 16 TXDEN (out), 17 GND (power), 18 RI# (in), 19 DCD# (in), 20 DSR# (in), 21 DTR# (out), 22 CTS# (in), 23 RTS# (out), 24 RXD (in), 25 TXD (out), 26 VCC (power), 27 XTIN (in), 28 XTOUT (out), 29 AGND (power), 30 AVCC (power), 31 TEST (in), 32 EECS (io), 33 Thermal Pad (power)

## IC_FT232HL
designator U?, comment FT232HL
Single channel,  High Speed USB <-> Serial/FIFO converter; Manufacturer: FTDI
footprint LQFP-48_N (48-Pin Thin Quad Flat Pack 0.5 mm Pitch, IPC Medium Density)
pins: 1 OSCI, 2 OSCO, 3 VPHY (power), 4 AGND (power), 5 REF (in), 6 USBDM, 7 USBDP, 8 VPLL (power), 9 AGND (power), 10 GND (power), 11 GND (power), 12 VCCIO (power), 13 ADBUS0 (io), 14 ADBUS1 (io), 15 ADBUS2 (io), 16 ADBUS3 (io), 17 ADBUS4 (io), 18 ADBUS5 (io), 19 ADBUS6 (io), 20 ADBUS7 (io), 21 ACBUS0 (io), 22 GND (power), 23 GND (power), 24 VCCIO (power), 25 ACBUS1 (io), 26 ACBUS2 (io), 27 ACBUS3 (io), 28 ACBUS4 (io), 29 ACBUS5 (io), 30 ACBUS6 (io), 31 ACBUS7 (io), 32 ACBUS8 (io), 33 ACBUS9 (io), 34 RESET# (in), 35 GND (power), 36 GND (power), 37 VCCA (power), 38 VCCCORE (power), 39 VCCD (power), 40 VREGIN (power), 41 AGND (power), 42 TEST, 43 EEDATA (io), 44 EECLK (out), 45 EECS (out), 46 VCCIO (power), 47 GND (power), 48 GND (power)

## IC_FT232HQ
designator U?, comment FT232HQ
Single channel,  High Speed USB <-> Serial/FIFO converter; Manufacturer: FTDI
footprint QFN50P800X800-48N (QFN, 48-Leads, Body 8.0x8.0mm (max), Pitch 0.50mm, IPC Medium Density)
pins: 1 OSCI, 2 OSCO, 3 VPHY (power), 4 AGND (power), 5 REF (in), 6 USBDM, 7 USBDP, 8 VPLL (power), 9 AGND (power), 10 GND (power), 11 GND (power), 12 VCCIO (power), 13 ADBUS0 (io), 14 ADBUS1 (io), 15 ADBUS2 (io), 16 ADBUS3 (io), 17 ADBUS4 (io), 18 ADBUS5 (io), 19 ADBUS6 (io), 20 ADBUS7 (io), 21 ACBUS0 (io), 22 GND (power), 23 GND (power), 24 VCCIO (power), 25 ACBUS1 (io), 26 ACBUS2 (io), 27 ACBUS3 (io), 28 ACBUS4 (io), 29 ACBUS5 (io), 30 ACBUS6 (io), 31 ACBUS7 (io), 32 ACBUS8 (io), 33 ACBUS9 (io), 34 RESET# (in), 35 GND (power), 36 GND (power), 37 VCCA (power), 38 VCCCORE (power), 39 VCCD (power), 40 VREGIN (power), 41 AGND (power), 42 TEST, 43 EEDATA (io), 44 EECLK (out), 45 EECS (out), 46 VCCIO (power), 47 GND (power), 48 GND (power), 49 GND (power)

## IC_FT232RL
designator U?, comment FT232RL
FTDI, USB <-> Serial
footprint SOP65P780-28N (SOP, 28-Leads, Body 10.2x5.3mm, Pitch 0.65mm, IPC Medium Density)
pins: 1 TXD, 2 ~{DTR}, 3 ~{RTS}, 4 VCCIO, 5 RXD, 6 ~{RI}, 7 GND, 8 NC hidden, 9 ~{DSR}, 10 ~{DCD}, 11 ~{CTS}, 12 CBUS4, 13 CBUS2, 14 CBUS3, 15 USBDP, 16 USBDM, 17 3V3OUT, 18 GND, 19 RESET#, 20 VCC, 21 GND, 22 CBUS1, 23 CBUS0, 24 VA3V3 hidden, 25 AGND, 26 TEST, 27 OSCI, 28 OSCO

## IC_FT232RL_For_Tester
designator U?, comment FT232RL
FTDI, USB <-> Serial
footprint SOP65P780-28N (SOP, 28-Leads, Body 10.2x5.3mm, Pitch 0.65mm, IPC Medium Density)
pins: 1 TXD, 2 ~{DTR}, 3 ~{RTS}, 4 VCCIO, 5 RXD, 6 ~{RI}, 7 GND, 8 NC hidden, 9 ~{DSR}, 10 ~{DCD}, 11 ~{CTS}, 12 CBUS4, 13 CBUS2, 14 CBUS3, 15 USBDP, 16 USBDM, 17 3V3OUT, 18 GND, 19 RESET#, 20 VCC, 21 GND, 22 CBUS1, 23 CBUS0, 24 VA3V3, 25 AGND, 26 TEST, 27 OSCI, 28 OSCO

## IC_FT232RQ
designator U?, comment FT232RQ
FTDI, USB <-> Serial
footprint QFN32_N (32-Pin Quad Flat No-Lead 0.5 mm Pitch, IPC Medium Density)
pins: 1 VCCIO, 2 RXD, 3 ~{RI}, 4 GND, 5 NC hidden, 6 ~{DSR}, 7 ~{DCD}, 8 ~{CTS}, 9 CBUS4, 10 CBUS2, 11 CBUS3, 12 NC hidden, 13 NC hidden, 14 USBDP, 15 USBDM, 16 3V3OUT, 17 GND, 18 RESET#, 19 VCC, 20 GND, 21 CBUS1, 22 CBUS0, 23 NC hidden, 24 AGND, 25 NC hidden, 26 TEST, 27 OSCI, 28 OSCO, 29 NC hidden, 30 TXD, 31 ~{DTR}, 32 ~{RTS}, 33 GND

## IC_FT232RQ_For_Tester
designator U?, comment FT232RQ
FTDI, USB <-> Serial
footprint SKT_S-MLF-00-032-A (Test & Burn socket for QFN-32, 0.5mm pitch, 5x5mm body. Emulation Technology S-MLF-00-032-A)
pins: 1 VCCIO, 2 RXD, 3 ~{RI}, 4 GND, 5 NC hidden, 6 ~{DSR}, 7 ~{DCD}, 8 ~{CTS}, 9 CBUS4, 10 CBUS2, 11 CBUS3, 12 NC hidden, 13 NC hidden, 14 USBDP, 15 USBDM, 16 3V3OUT, 17 GND, 18 RESET#, 19 VCC, 20 GND, 21 CBUS1, 22 CBUS0, 23 VCCA, 24 AGND, 25 NC hidden, 26 TEST, 27 OSCI, 28 OSCO, 29 NC hidden, 30 TXD, 31 ~{DTR}, 32 ~{RTS}, 33 GND

## IC_FT240XQ
designator U?, comment FT240XQ
FT240XQ-QFN-24
footprint VQFN50P400X400X90-24N (QFN, 24-Leads, Body 4.0x4.0mm (max), Pitch 0.50mm, IPC Medium Density)
pins: 1 DATA1 (io), 2 DATA7 (io), 3 GND (power), 4 DATA5 (io), 5 DATA6 (io), 6 DATA3 (io), 7 SI/WU# (io), 8 RD# (io), 9 WR# (io), 10 USBDP (io), 11 USBDM (io), 12 3V3OUT (power), 13 RESET# (in), 14 VCORE (power), 15 VCC (power), 16 GND (power), 17 TXE# (io), 18 RXF# (io), 19 CBUS6 (io), 20 CBUS5 (io), 21 DATA0 (io), 22 DATA4 (io), 23 DATA2 (io), 24 VCCIO (power), 25 GND (power)

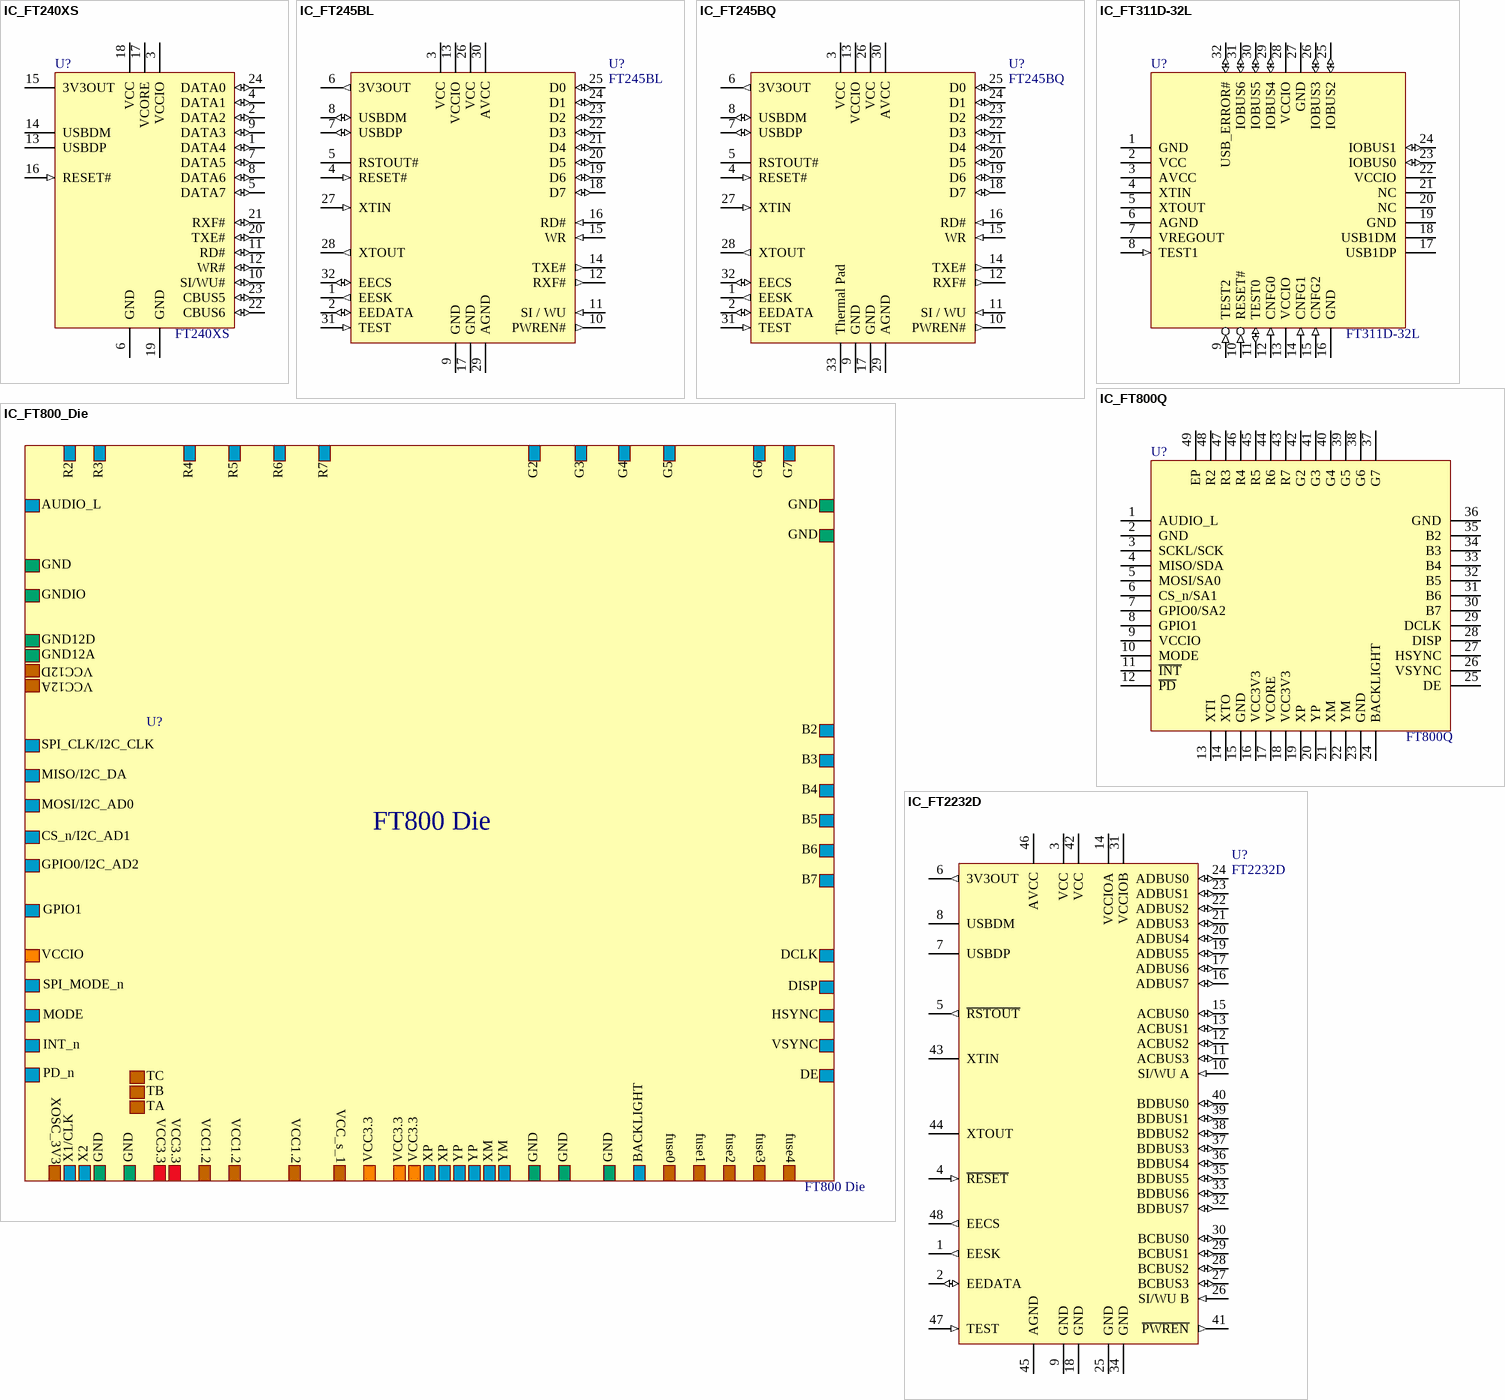
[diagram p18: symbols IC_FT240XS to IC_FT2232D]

## IC_FT240XS
designator U?, comment FT240XS
FT240XS-SSOP-24
footprint SSOP635P600X175-24N (SSOP, 24-Leads, Body 8.7x4.0mm (max), Pitch 0.635mm, IPC Medium Density)
pins: 1 DATA4 (io), 2 DATA2 (io), 3 VCCIO (power), 4 DATA1 (io), 5 DATA7 (io), 6 GND (power), 7 DATA5 (io), 8 DATA6 (io), 9 DATA3 (io), 10 SI/WU# (io), 11 RD# (io), 12 WR# (io), 13 USBDP, 14 USBDM, 15 3V3OUT (power), 16 RESET# (in), 17 VCORE (power), 18 VCC (power), 19 GND (power), 20 TXE# (io), 21 RXF# (io), 22 CBUS6 (io), 23 CBUS5 (io), 24 DATA0 (io)

## IC_FT245BL
designator U?, comment FT245BL
USB/Parallel FIFO Bi-Directional Data Transfer Chip, LQFP-32, Pb-Free; Manufacturer: Future Technology Devices International Ltd. (FTDI)
footprint LQFP-32_N (Thin QFP, 32-Leads, Body 7x7mm, Pitch 0.8mm, IPC Medium Density)
pins: 1 EESK (out) "Clock signal to EEPROM. Adding a 10K pull down resistor onto EESK will cause the FT245BM to use USB Product ID 6005 (hex) instead of 6001 (hex). All of the other USB device descriptors are unchanged.", 2 EEDATA (io) "EEPROM - Data I/O Connect directly to Data-In of the EEPROM and to Data-Out of the EEPROM via a 2.2K resistor. Also pull Data-Out of the EEPROM to VCC via a 10K resistor for correct operation.", 3 VCC (power) "+4.35 volt to +5.25 volt VCC to the device core, LDO and none-FIFO interface pins.", 4 RESET# (in) "Can be used by an external device to reset the FT245BM. If not required, tie to VCC.", 5 RSTOUT# (hiz) "Output of the internal Reset Generator. Stays high impedance for 5ms after VCC > 3.5V and the internal clock starts up, then clamps its output to the 3.3V output of the internal regulator.", 6 3V3OUT (out) "3.3 volt Output from the integrated L.D.O. regulator This pin should be decoupled to GND using a 33nF ceramic capacitor in close proximity to the device pin.", 7 USBDP (io) "USB Data Signal Plus (Requires 1.5K pull-up to 3V3OUT or RSTOUT#)", 8 USBDM (io) "USB Data Signal Minus", 9 GND (power) "Device - Ground Supply Pins", 10 PWREN# (out) "Goes Low after the device is configured via USB, then high during USB suspend. Can be used to control power to external logic using a P-Channel MOSFET switch. Enable the Interface Pull-Down Option in EEPROM when using the PWREN# pin in this way.", 11 SI / WU (in) "Send Immediate / WakeUp. Tie this pin to VCCIO if not used.", 12 RXF# (out) "When high, do not read data from the FIFO. When low, there is data available in the FIFO which can be read by strobing RD# low then high again.", 13 VCCIO (power) "+3.0 volt to +5.25 volt VCC to the FIFO interface pins 10..12, 14..16 and 18..25.", 14 TXE# (out) "When high, do not write data into the FIFO. When low, data can be written into the FIFO by strobing WR high then low.", 15 WR (in) "Writes the Data Byte on the D0..D7 into the Transmit FIFO Buffer when WR goes from high to low.", 16 RD# (in) "Enables Current FIFO Data Byte on D0..D7 when low. Fetches the next FIFO Data Byte (if available) from the Receive FIFO Buffer when RD# goes from low to high.", 17 GND (power) "Device - Ground Supply Pins", 18 D7 (io) "FIFO Data Bus Bit 7", 19 D6 (io) "FIFO Data Bus Bit 6", 20 D5 (io) "FIFO Data Bus Bit 5", 21 D4 (io) "FIFO Data Bus Bit 4", 22 D3 (io) "FIFO Data Bus Bit 3", 23 D2 (io) "FIFO Data Bus Bit 2", 24 D1 (io) "FIFO Data Bus Bit 1", 25 D0 (io) "FIFO Data Bus Bit 0", 26 VCC (power) "+4.35 volt to +5.25 volt VCC to the device core, LDO and none-FIFO interface pins.", 27 XTIN (in) "Input to 6MHz Crystal Oscillator. Can also be driven by an external 6MHz clock. Note : Switching threshold of this pin is VCC/2, so if driving from an external source, the source must be driving at 5V CMOS level or a.c. coupled to centre around VCC/2.", 28 XTOUT (out) "Output from 6MHz Crystal Oscillator Cell. XTOUT stops oscillating during USB suspend, so take care if using this signal to clock external logic.", 29 AGND (power) "Device - Analog Ground Supply for the internal x8 clock multiplier", 30 AVCC (power) "Device - Analog Power Supply for the internal x8 clock multiplier", 31 TEST (in) "Puts device in I.C. test mode – must be tied to GND for normal operation.", 32 EECS (io) "EEPROM - Chip Select. For 48MHz operation pull EECS to GND using a 10K resistor. For 6MHz operation no resistor is required."

## IC_FT245BQ
designator U?, comment FT245BQ
USB/Parallel FIFO Bi-Directional Data Transfer Chip, QFN32, Pb-Free; Manufacturer: Future Technology Devices International Ltd. (FTDI)
footprint VQFN50P500X500-X90-32N (QFN, 32-Leads, Body 5.1x5.1mm (max), Pitch 0.50mm, IPC Medium Density)
pins: 1 EESK (out) "Clock signal to EEPROM. Adding a 10K pull down resistor onto EESK will cause the FT245BM to use USB Product ID 6005 (hex) instead of 6001 (hex). All of the other USB device descriptors are unchanged.", 2 EEDATA (io) "EEPROM - Data I/O Connect directly to Data-In of the EEPROM and to Data-Out of the EEPROM via a 2.2K resistor. Also pull Data-Out of the EEPROM to VCC via a 10K resistor for correct operation.", 3 VCC (power) "+4.35 volt to +5.25 volt VCC to the device core, LDO and none-FIFO interface pins.", 4 RESET# (in) "Can be used by an external device to reset the FT245BM. If not required, tie to VCC.", 5 RSTOUT# (hiz) "Output of the internal Reset Generator. Stays high impedance for 5ms after VCC > 3.5V and the internal clock starts up, then clamps its output to the 3.3V output of the internal regulator.", 6 3V3OUT (out) "3.3 volt Output from the integrated L.D.O. regulator This pin should be decoupled to GND using a 33nF ceramic capacitor in close proximity to the device pin.", 7 USBDP (io) "USB Data Signal Plus (Requires 1.5K pull-up to 3V3OUT or RSTOUT#)", 8 USBDM (io) "USB Data Signal Minus", 9 GND (power) "Device - Ground Supply Pins", 10 PWREN# (out) "Goes Low after the device is configured via USB, then high during USB suspend. Can be used to control power to external logic using a P-Channel MOSFET switch. Enable the Interface Pull-Down Option in EEPROM when using the PWREN# pin in this way.", 11 SI / WU (in) "Send Immediate / WakeUp. Tie this pin to VCCIO if not used.", 12 RXF# (out) "When high, do not read data from the FIFO. When low, there is data available in the FIFO which can be read by strobing RD# low then high again.", 13 VCCIO (power) "+3.0 volt to +5.25 volt VCC to the FIFO interface pins 10..12, 14..16 and 18..25.", 14 TXE# (out) "When high, do not write data into the FIFO. When low, data can be written into the FIFO by strobing WR high then low.", 15 WR (in) "Writes the Data Byte on the D0..D7 into the Transmit FIFO Buffer when WR goes from high to low.", 16 RD# (in) "Enables Current FIFO Data Byte on D0..D7 when low. Fetches the next FIFO Data Byte (if available) from the Receive FIFO Buffer when RD# goes from low to high.", 17 GND (power) "Device - Ground Supply Pins", 18 D7 (io) "FIFO Data Bus Bit 7", 19 D6 (io) "FIFO Data Bus Bit 6", 20 D5 (io) "FIFO Data Bus Bit 5", 21 D4 (io) "FIFO Data Bus Bit 4", 22 D3 (io) "FIFO Data Bus Bit 3", 23 D2 (io) "FIFO Data Bus Bit 2", 24 D1 (io) "FIFO Data Bus Bit 1", 25 D0 (io) "FIFO Data Bus Bit 0", 26 VCC (power) "+4.35 volt to +5.25 volt VCC to the device core, LDO and none-FIFO interface pins.", 27 XTIN (in) "Input to 6MHz Crystal Oscillator. Can also be driven by an external 6MHz clock. Note : Switching threshold of this pin is VCC/2, so if driving from an external source, the source must be driving at 5V CMOS level or a.c. coupled to centre around VCC/2.", 28 XTOUT (out) "Output from 6MHz Crystal Oscillator Cell. XTOUT stops oscillating during USB suspend, so take care if using this signal to clock external logic.", 29 AGND (power) "Device - Analog Ground Supply for the internal x8 clock multiplier", 30 AVCC (power) "Device - Analog Power Supply for the internal x8 clock multiplier", 31 TEST (in) "Puts device in I.C. test mode – must be tied to GND for normal operation.", 32 EECS (io) "EEPROM - Chip Select. For 48MHz operation pull EECS to GND using a 10K resistor. For 6MHz operation no resistor is required.", 33 Thermal Pad (power)

## IC_FT311D-32L
designator U?, comment FT311D-32L
footprint LQFP-32_N (32-Pin Thin Quad Flat Pack 0.8 mm Pitch, IPC Medium Density)
pins: 1 GND (power), 2 VCC (power), 3 AVCC (power), 4 XTIN, 5 XTOUT, 6 AGND (power), 7 VREGOUT (power), 8 TEST1 (in), 9 TEST2 (in), 10 RESET# (in), 11 TEST0 (io), 12 CNFG0 (in), 13 VCCIO (power), 14 CNFG1 (in), 15 CNFG2 (in), 16 GND (power), 17 USB1DP, 18 USB1DM, 19 GND (power), 20 NC, 21 NC, 22 VCCIO (power), 23 IOBUS0 (io), 24 IOBUS1 (io), 25 IOBUS2 (io), 26 IOBUS3 (io), 27 GND (power), 28 VCCIO (power), 29 IOBUS4 (io), 30 IOBUS5 (io), 31 IOBUS6 (io), 32 USB_ERROR# (io)

## IC_FT800_Die
designator U?, comment FT800 Die
Not for customer designs

## IC_FT800Q
designator U?, comment FT800Q
Not for customer designs
footprint QFN50P700X700-48N (QFN, 48-Leads, Body 7.0x7.0mm (max), Pitch 0.50mm, IPC Medium Density)
pins: 1 AUDIO_L, 2 GND, 3 SCKL/SCK, 4 MISO/SDA, 5 MOSI/SA0, 6 CS_n/SA1, 7 GPIO0/SA2, 8 GPIO1, 9 VCCIO, 10 MODE, 11 ~{INT}, 12 ~{PD}, 13 XTI, 14 XTO, 15 GND, 16 VCC3V3, 17 VCORE, 18 VCC3V3, 19 XP, 20 YP, 21 XM, 22 YM, 23 GND, 24 BACKLIGHT, 25 DE, 26 VSYNC, 27 HSYNC, 28 DISP, 29 DCLK, 30 B7, 31 B6, 32 B5, 33 B4, 34 B3, 35 B2, 36 GND, 37 G7, 38 G6, 39 G5, 40 G4, 41 G3, 42 G2, 43 R7, 44 R6, 45 R5, 46 R4, 47 R3, 48 R2, 49 EP

## IC_FT2232D
designator U?, comment FT2232D
2 Channel USB <-> RS232 Bridge; LQFP-48
footprint LQFP-48_N (48-Pin Thin Quad Flat Pack 0.5 mm Pitch, IPC Medium Density)
pins: 1 EESK (out), 2 EEDATA (io), 3 VCC (power), 4 ~{RESET} (in), 5 ~{RSTOUT} (out), 6 3V3OUT (out), 7 USBDP, 8 USBDM, 9 GND (power), 10 SI/WU A (in), 11 ACBUS3 (io), 12 ACBUS2 (io), 13 ACBUS1 (io), 14 VCCIOA (power), 15 ACBUS0 (io), 16 ADBUS7 (io), 17 ADBUS6 (io), 18 GND (power), 19 ADBUS5 (io), 20 ADBUS4 (io), 21 ADBUS3 (io), 22 ADBUS2 (io), 23 ADBUS1 (io), 24 ADBUS0 (io), 25 GND (power), 26 SI/WU B (in), 27 BCBUS3 (io), 28 BCBUS2 (io), 29 BCBUS1 (io), 30 BCBUS0 (io), 31 VCCIOB (power), 32 BDBUS7 (io), 33 BDBUS6 (io), 34 GND (power), 35 BDBUS5 (io), 36 BDBUS4 (io), 37 BDBUS3 (io), 38 BDBUS2 (io), 39 BDBUS1 (io), 40 BDBUS0 (io), 41 ~{PWREN} (out), 42 VCC (power), 43 XTIN, 44 XTOUT, 45 AGND (power), 46 AVCC (power), 47 TEST (in), 48 EECS (out)

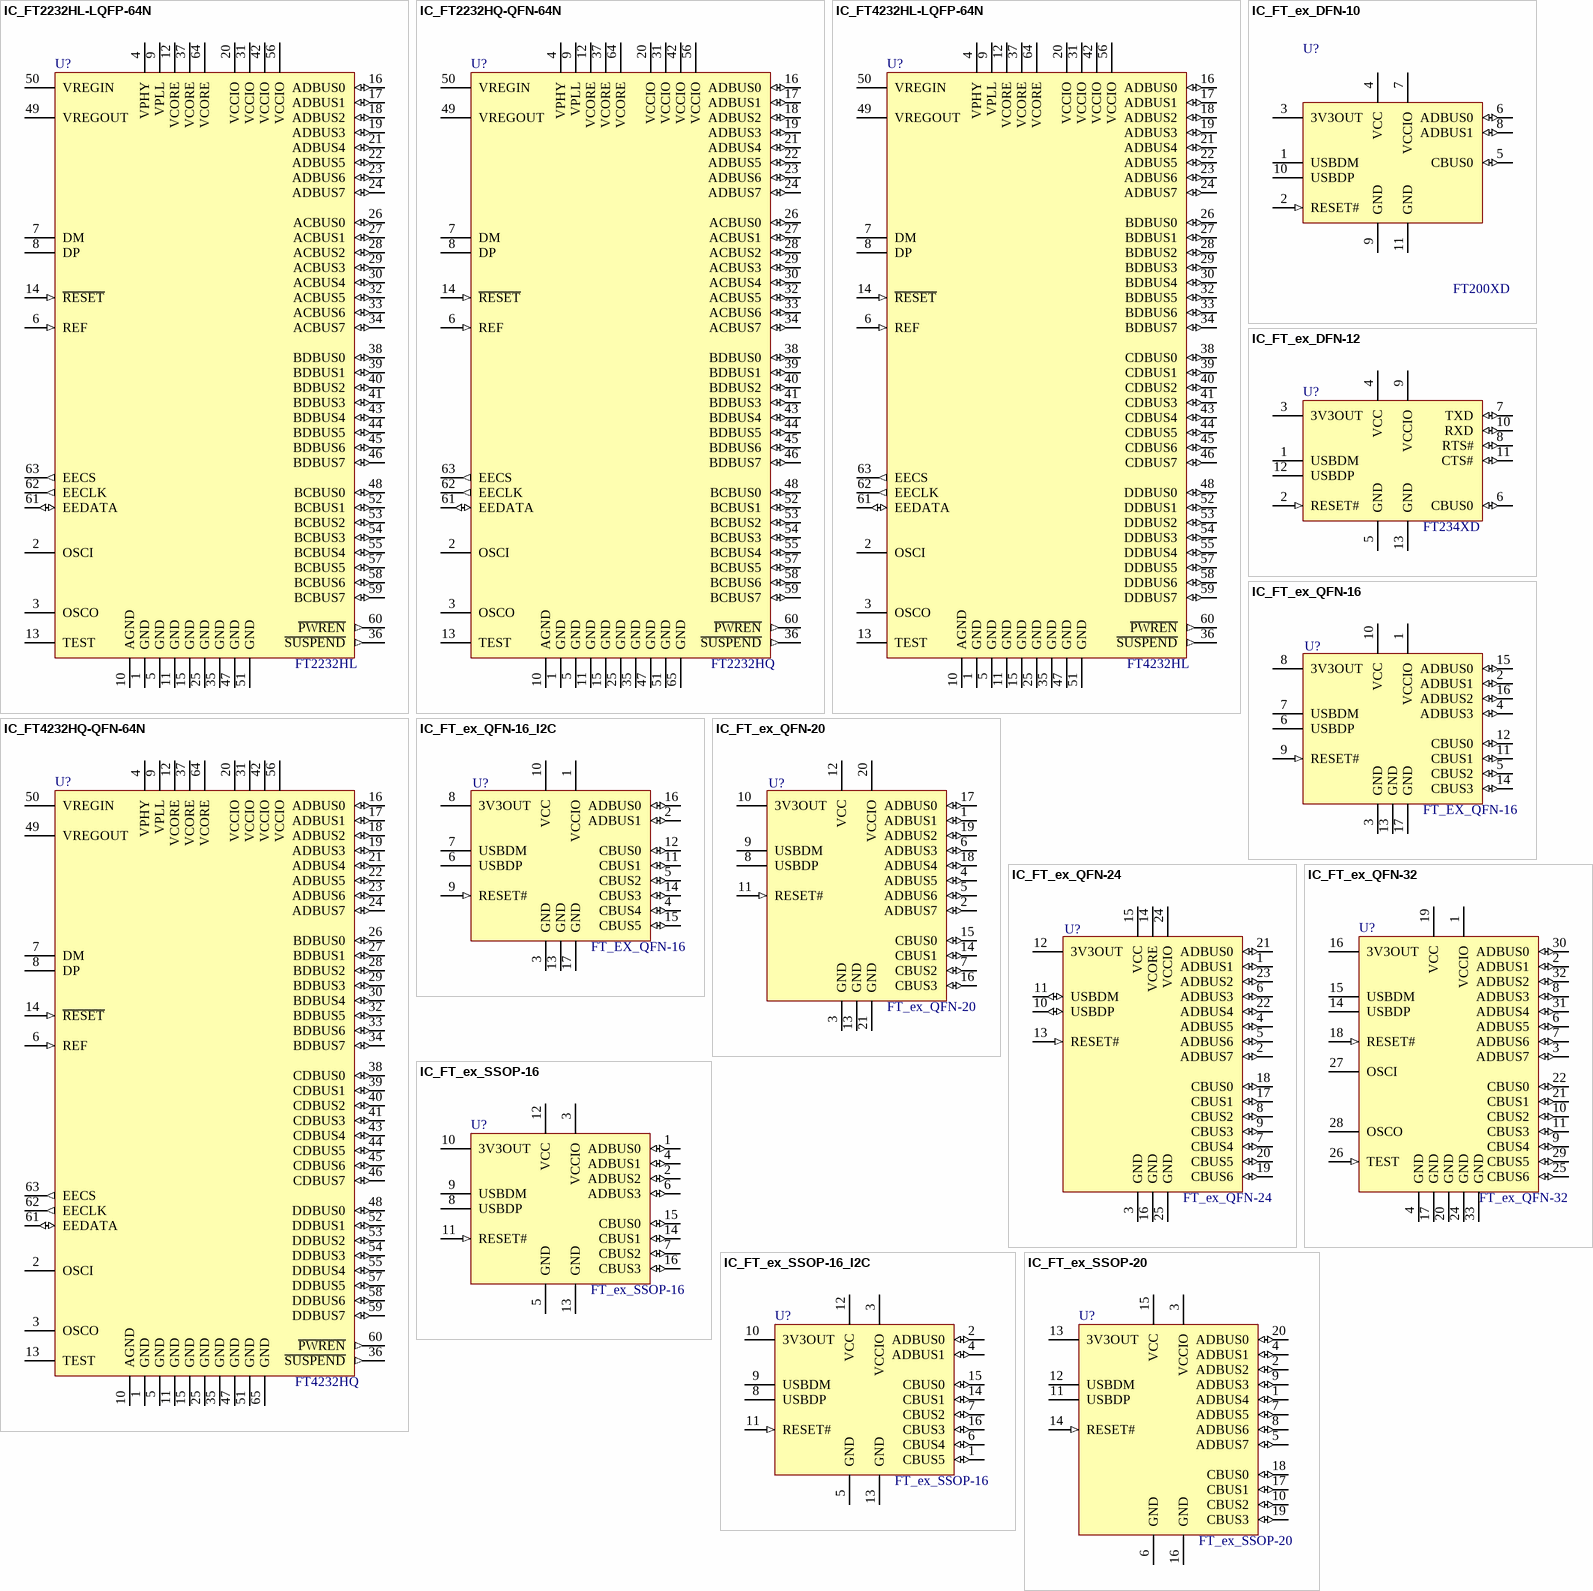
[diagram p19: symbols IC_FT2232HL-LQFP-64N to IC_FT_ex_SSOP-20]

## IC_FT2232HL-LQFP-64N
designator U?, comment FT2232HL
Dual channel,  High Speed USB <-> RS232/FIFO converter; Manufacturer: FTDI
footprint LQFP50P10X10-64N (LQFP, 64-Leads, Body 10x10mm (max), Pitch 0.50mm, IPC Medium Density)
pins: 1 GND (power), 2 OSCI, 3 OSCO, 4 VPHY (power), 5 GND (power), 6 REF (in), 7 DM, 8 DP, 9 VPLL (power), 10 AGND (power), 11 GND (power), 12 VCORE (power), 13 TEST, 14 ~{RESET} (in), 15 GND (power), 16 ADBUS0 (io), 17 ADBUS1 (io), 18 ADBUS2 (io), 19 ADBUS3 (io), 20 VCCIO (power), 21 ADBUS4 (io), 22 ADBUS5 (io), 23 ADBUS6 (io), 24 ADBUS7 (io), 25 GND (power), 26 ACBUS0 (io), 27 ACBUS1 (io), 28 ACBUS2 (io), 29 ACBUS3 (io), 30 ACBUS4 (io), 31 VCCIO (power), 32 ACBUS5 (io), 33 ACBUS6 (io), 34 ACBUS7 (io), 35 GND (power), 36 ~{SUSPEND} (out), 37 VCORE (power), 38 BDBUS0 (io), 39 BDBUS1 (io), 40 BDBUS2 (io), 41 BDBUS3 (io), 42 VCCIO (power), 43 BDBUS4 (io), 44 BDBUS5 (io), 45 BDBUS6 (io), 46 BDBUS7 (io), 47 GND (power), 48 BCBUS0 (io), 49 VREGOUT (power), 50 VREGIN (power), 51 GND (power), 52 BCBUS1 (io), 53 BCBUS2 (io), 54 BCBUS3 (io), 55 BCBUS4 (io), 56 VCCIO (power), 57 BCBUS5 (io), 58 BCBUS6 (io), 59 BCBUS7 (io), 60 ~{PWREN} (out), 61 EEDATA (io), 62 EECLK (out), 63 EECS (out), 64 VCORE (power)

## IC_FT2232HQ-QFN-64N
designator U?, comment FT2232HQ
Dual channel,  High Speed USB <-> RS232/FIFO converter; Manufacturer: FTDI
footprint QFN50P900X900-64N (QFN, 64-Leads, Body 9x9mm, Pitch 0.50mm, IPC Medium Density)
pins: 1 GND (power), 2 OSCI, 3 OSCO, 4 VPHY (power), 5 GND (power), 6 REF (in), 7 DM, 8 DP, 9 VPLL (power), 10 AGND (power), 11 GND (power), 12 VCORE (power), 13 TEST, 14 ~{RESET} (in), 15 GND (power), 16 ADBUS0 (io), 17 ADBUS1 (io), 18 ADBUS2 (io), 19 ADBUS3 (io), 20 VCCIO (power), 21 ADBUS4 (io), 22 ADBUS5 (io), 23 ADBUS6 (io), 24 ADBUS7 (io), 25 GND (power), 26 ACBUS0 (io), 27 ACBUS1 (io), 28 ACBUS2 (io), 29 ACBUS3 (io), 30 ACBUS4 (io), 31 VCCIO (power), 32 ACBUS5 (io), 33 ACBUS6 (io), 34 ACBUS7 (io), 35 GND (power), 36 ~{SUSPEND} (out), 37 VCORE (power), 38 BDBUS0 (io), 39 BDBUS1 (io), 40 BDBUS2 (io), 41 BDBUS3 (io), 42 VCCIO (power), 43 BDBUS4 (io), 44 BDBUS5 (io), 45 BDBUS6 (io), 46 BDBUS7 (io), 47 GND (power), 48 BCBUS0 (io), 49 VREGOUT (power), 50 VREGIN (power), 51 GND (power), 52 BCBUS1 (io), 53 BCBUS2 (io), 54 BCBUS3 (io), 55 BCBUS4 (io), 56 VCCIO (power), 57 BCBUS5 (io), 58 BCBUS6 (io), 59 BCBUS7 (io), 60 ~{PWREN} (out), 61 EEDATA (io), 62 EECLK (out), 63 EECS (out), 64 VCORE (power), 65 GND (power)

## IC_FT4232HL-LQFP-64N
designator U?, comment FT4232HL
Quad channel,  High Speed USB <-> RS232/FIFO converter; Manufacturer: FTDI
footprint LQFP50P10X10-64N (LQFP, 64-Leads, Body 10x10mm (max), Pitch 0.50mm, IPC Medium Density)
pins: 1 GND (power), 2 OSCI, 3 OSCO, 4 VPHY (power), 5 GND (power), 6 REF (in), 7 DM, 8 DP, 9 VPLL (power), 10 AGND (power), 11 GND (power), 12 VCORE (power), 13 TEST, 14 ~{RESET} (in), 15 GND (power), 16 ADBUS0 (io), 17 ADBUS1 (io), 18 ADBUS2 (io), 19 ADBUS3 (io), 20 VCCIO (power), 21 ADBUS4 (io), 22 ADBUS5 (io), 23 ADBUS6 (io), 24 ADBUS7 (io), 25 GND (power), 26 BDBUS0 (io), 27 BDBUS1 (io), 28 BDBUS2 (io), 29 BDBUS3 (io), 30 BDBUS4 (io), 31 VCCIO (power), 32 BDBUS5 (io), 33 BDBUS6 (io), 34 BDBUS7 (io), 35 GND (power), 36 ~{SUSPEND} (out), 37 VCORE (power), 38 CDBUS0 (io), 39 CDBUS1 (io), 40 CDBUS2 (io), 41 CDBUS3 (io), 42 VCCIO (power), 43 CDBUS4 (io), 44 CDBUS5 (io), 45 CDBUS6 (io), 46 CDBUS7 (io), 47 GND (power), 48 DDBUS0 (io), 49 VREGOUT (power), 50 VREGIN (power), 51 GND (power), 52 DDBUS1 (io), 53 DDBUS2 (io), 54 DDBUS3 (io), 55 DDBUS4 (io), 56 VCCIO (power), 57 DDBUS5 (io), 58 DDBUS6 (io), 59 DDBUS7 (io), 60 ~{PWREN} (out), 61 EEDATA (io), 62 EECLK (out), 63 EECS (out), 64 VCORE (power)

## IC_FT4232HQ-QFN-64N
designator U?, comment FT4232HQ
Quad channel,  High Speed USB <-> RS232/FIFO converter; Manufacturer: FTDI
footprint QFN50P900X900-64N (QFN, 64-Leads, Body 9x9mm, Pitch 0.50mm, IPC Medium Density)
pins: 1 GND (power), 2 OSCI, 3 OSCO, 4 VPHY (power), 5 GND (power), 6 REF (in), 7 DM, 8 DP, 9 VPLL (power), 10 AGND (power), 11 GND (power), 12 VCORE (power), 13 TEST, 14 ~{RESET} (in), 15 GND (power), 16 ADBUS0 (io), 17 ADBUS1 (io), 18 ADBUS2 (io), 19 ADBUS3 (io), 20 VCCIO (power), 21 ADBUS4 (io), 22 ADBUS5 (io), 23 ADBUS6 (io), 24 ADBUS7 (io), 25 GND (power), 26 BDBUS0 (io), 27 BDBUS1 (io), 28 BDBUS2 (io), 29 BDBUS3 (io), 30 BDBUS4 (io), 31 VCCIO (power), 32 BDBUS5 (io), 33 BDBUS6 (io), 34 BDBUS7 (io), 35 GND (power), 36 ~{SUSPEND} (out), 37 VCORE (power), 38 CDBUS0 (io), 39 CDBUS1 (io), 40 CDBUS2 (io), 41 CDBUS3 (io), 42 VCCIO (power), 43 CDBUS4 (io), 44 CDBUS5 (io), 45 CDBUS6 (io), 46 CDBUS7 (io), 47 GND (power), 48 DDBUS0 (io), 49 VREGOUT (power), 50 VREGIN (power), 51 GND (power), 52 DDBUS1 (io), 53 DDBUS2 (io), 54 DDBUS3 (io), 55 DDBUS4 (io), 56 VCCIO (power), 57 DDBUS5 (io), 58 DDBUS6 (io), 59 DDBUS7 (io), 60 ~{PWREN} (out), 61 EEDATA (io), 62 EECLK (out), 63 EECS (out), 64 VCORE (power), 65 GND (power)

## IC_FT_ex_DFN-10
designator U?, comment FT200XD
FT_ex DFN-10; Do not use on customer designs
pins: 1 USBDM, 2 RESET# (in), 3 3V3OUT (power), 4 VCC (power), 5 CBUS0 (io), 6 ADBUS0 (io), 7 VCCIO (power), 8 ADBUS1 (io), 9 GND (power), 10 USBDP, 11 GND (power)

## IC_FT_ex_DFN-12
designator U?, comment FT234XD
FT_ex_DFN-12; Do not use for customer designs
pins: 1 USBDM, 2 RESET# (in), 3 3V3OUT (power), 4 VCC (power), 5 GND (power), 6 CBUS0 (io), 7 TXD (io), 8 RTS# (io), 9 VCCIO (power), 10 RXD (io), 11 CTS# (io), 12 USBDP, 13 GND (power)

## IC_FT_ex_QFN-16
designator U?, comment FT_EX_QFN-16
FT_ex-QFN-16; Do not use on customer designs
footprint VQFN65P400X400X90-16N (VQFN, 16-Leads, Body 4.0x4.0mm (max), Pitch 0.65mm, IPC Medium Density)
pins: 1 VCCIO (power), 2 ADBUS1 (io), 3 GND (power), 4 ADBUS3 (io), 5 CBUS2 (io), 6 USBDP, 7 USBDM, 8 3V3OUT (power), 9 RESET# (in), 10 VCC (power), 11 CBUS1 (io), 12 CBUS0 (io), 13 GND (power), 14 CBUS3 (io), 15 ADBUS0 (io), 16 ADBUS2 (io), 17 GND (power)

## IC_FT_ex_QFN-16_I2C
designator U?, comment FT_EX_QFN-16
FT_ex-QFN-16; Do not use on customer designs
footprint VQFN65P400X400X90-16N (VQFN, 16-Leads, Body 4.0x4.0mm (max), Pitch 0.65mm, IPC Medium Density)
pins: 1 VCCIO (power), 2 ADBUS1 (io), 3 GND (power), 4 CBUS4 (io), 5 CBUS2 (io), 6 USBDP, 7 USBDM, 8 3V3OUT (power), 9 RESET# (in), 10 VCC (power), 11 CBUS1 (io), 12 CBUS0 (io), 13 GND (power), 14 CBUS3 (io), 15 CBUS5 (io), 16 ADBUS0 (io), 17 GND (power)

## IC_FT_ex_QFN-20
designator U?, comment FT_ex_QFN-20
FT_ex-QFN-20; Do not use on customer designs
footprint VQFN50P400X400X90-20N (VQFN, 20-Leads, Body 4.0x4.0mm (max), Pitch 0.50mm, IPC Medium Density)
pins: 1 ADBUS1 (io), 2 ADBUS7 (io), 3 GND (power), 4 ADBUS5 (io), 5 ADBUS6 (io), 6 ADBUS3 (io), 7 CBUS2 (io), 8 USBDP, 9 USBDM, 10 3V3OUT (power), 11 RESET# (in), 12 VCC (power), 13 GND (power), 14 CBUS1 (io), 15 CBUS0 (io), 16 CBUS3 (io), 17 ADBUS0 (io), 18 ADBUS4 (io), 19 ADBUS2 (io), 20 VCCIO (power), 21 GND (power)

## IC_FT_ex_QFN-24
designator U?, comment FT_ex_QFN-24
FT_ex-QFN-24; Do not use on customer designs
footprint VQFN50P400X400X90-24N (QFN, 24-Leads, Body 4.0x4.0mm (max), Pitch 0.50mm, IPC Medium Density)
pins: 1 ADBUS1 (io), 2 ADBUS7 (io), 3 GND (power), 4 ADBUS5 (io), 5 ADBUS6 (io), 6 ADBUS3 (io), 7 CBUS4 (io), 8 CBUS2 (io), 9 CBUS3 (io), 10 USBDP (io), 11 USBDM (io), 12 3V3OUT (power), 13 RESET# (in), 14 VCORE (power), 15 VCC (power), 16 GND (power), 17 CBUS1 (io), 18 CBUS0 (io), 19 CBUS6 (io), 20 CBUS5 (io), 21 ADBUS0 (io), 22 ADBUS4 (io), 23 ADBUS2 (io), 24 VCCIO (power), 25 GND (power)

## IC_FT_ex_QFN-32
designator U?, comment FT_ex_QFN-32
FT_ex-QFN-32; Do not use on customer designs
pins: 1 VCCIO (power), 2 ADBUS1 (io), 3 ADBUS7 (io), 4 GND (power), 5 NC hidden, 6 ADBUS5 (io), 7 ADBUS6 (io), 8 ADBUS3 (io), 9 CBUS4 (io), 10 CBUS2 (io), 11 CBUS3 (io), 12 NC hidden, 13 NC hidden, 14 USBDP, 15 USBDM, 16 3V3OUT (power), 17 GND (power), 18 RESET# (in), 19 VCC (power), 20 GND (power), 21 CBUS1 (io), 22 CBUS0 (io), 23 NC hidden, 24 GND (power), 25 CBUS6 (io), 26 TEST (in), 27 OSCI, 28 OSCO, 29 CBUS5 (io), 30 ADBUS0 (io), 31 ADBUS4 (io), 32 ADBUS2 (io), 33 GND (power)

## IC_FT_ex_SSOP-16
designator U?, comment FT_ex_SSOP-16
FT_ex-SSOP-16; Do not use on customer designs
footprint SSOP635P600X175-16N (SSOP, 16-Leads, Body 4.9x3.9mm (max), Pitch 0.635mm, IPC Medium Density)
pins: 1 ADBUS0 (io), 2 ADBUS2 (io), 3 VCCIO (power), 4 ADBUS1 (io), 5 GND (power), 6 ADBUS3 (io), 7 CBUS2 (io), 8 USBDP, 9 USBDM, 10 3V3OUT (power), 11 RESET# (in), 12 VCC (power), 13 GND (power), 14 CBUS1 (io), 15 CBUS0 (io), 16 CBUS3 (io)

## IC_FT_ex_SSOP-16_I2C
designator U?, comment FT_ex_SSOP-16
FT_ex-SSOP-16; Do not use on customer designs
footprint SSOP635P600X175-16N (SSOP, 16-Leads, Body 4.9x3.9mm (max), Pitch 0.635mm, IPC Medium Density)
pins: 1 CBUS5 (io), 2 ADBUS0 (io), 3 VCCIO (power), 4 ADBUS1 (io), 5 GND (power), 6 CBUS4 (io), 7 CBUS2 (io), 8 USBDP, 9 USBDM, 10 3V3OUT (power), 11 RESET# (in), 12 VCC (power), 13 GND (power), 14 CBUS1 (io), 15 CBUS0 (io), 16 CBUS3 (io)

## IC_FT_ex_SSOP-20
designator U?, comment FT_ex_SSOP-20
FT_ex-SSOP-20; Do not use on customer designs
footprint SSOP635P600X175-20N (SSOP, 20-Leads, Body 8.7x4.0mm (max), Pitch 0.635mm, IPC Medium Density)
pins: 1 ADBUS4 (io), 2 ADBUS2 (io), 3 VCCIO (power), 4 ADBUS1 (io), 5 ADBUS7 (io), 6 GND (power), 7 ADBUS5 (io), 8 ADBUS6 (io), 9 ADBUS3 (io), 10 CBUS2 (io), 11 USBDP, 12 USBDM, 13 3V3OUT (power), 14 RESET# (in), 15 VCC (power), 16 GND (power), 17 CBUS1 (io), 18 CBUS0 (io), 19 CBUS3 (io), 20 ADBUS0 (io)

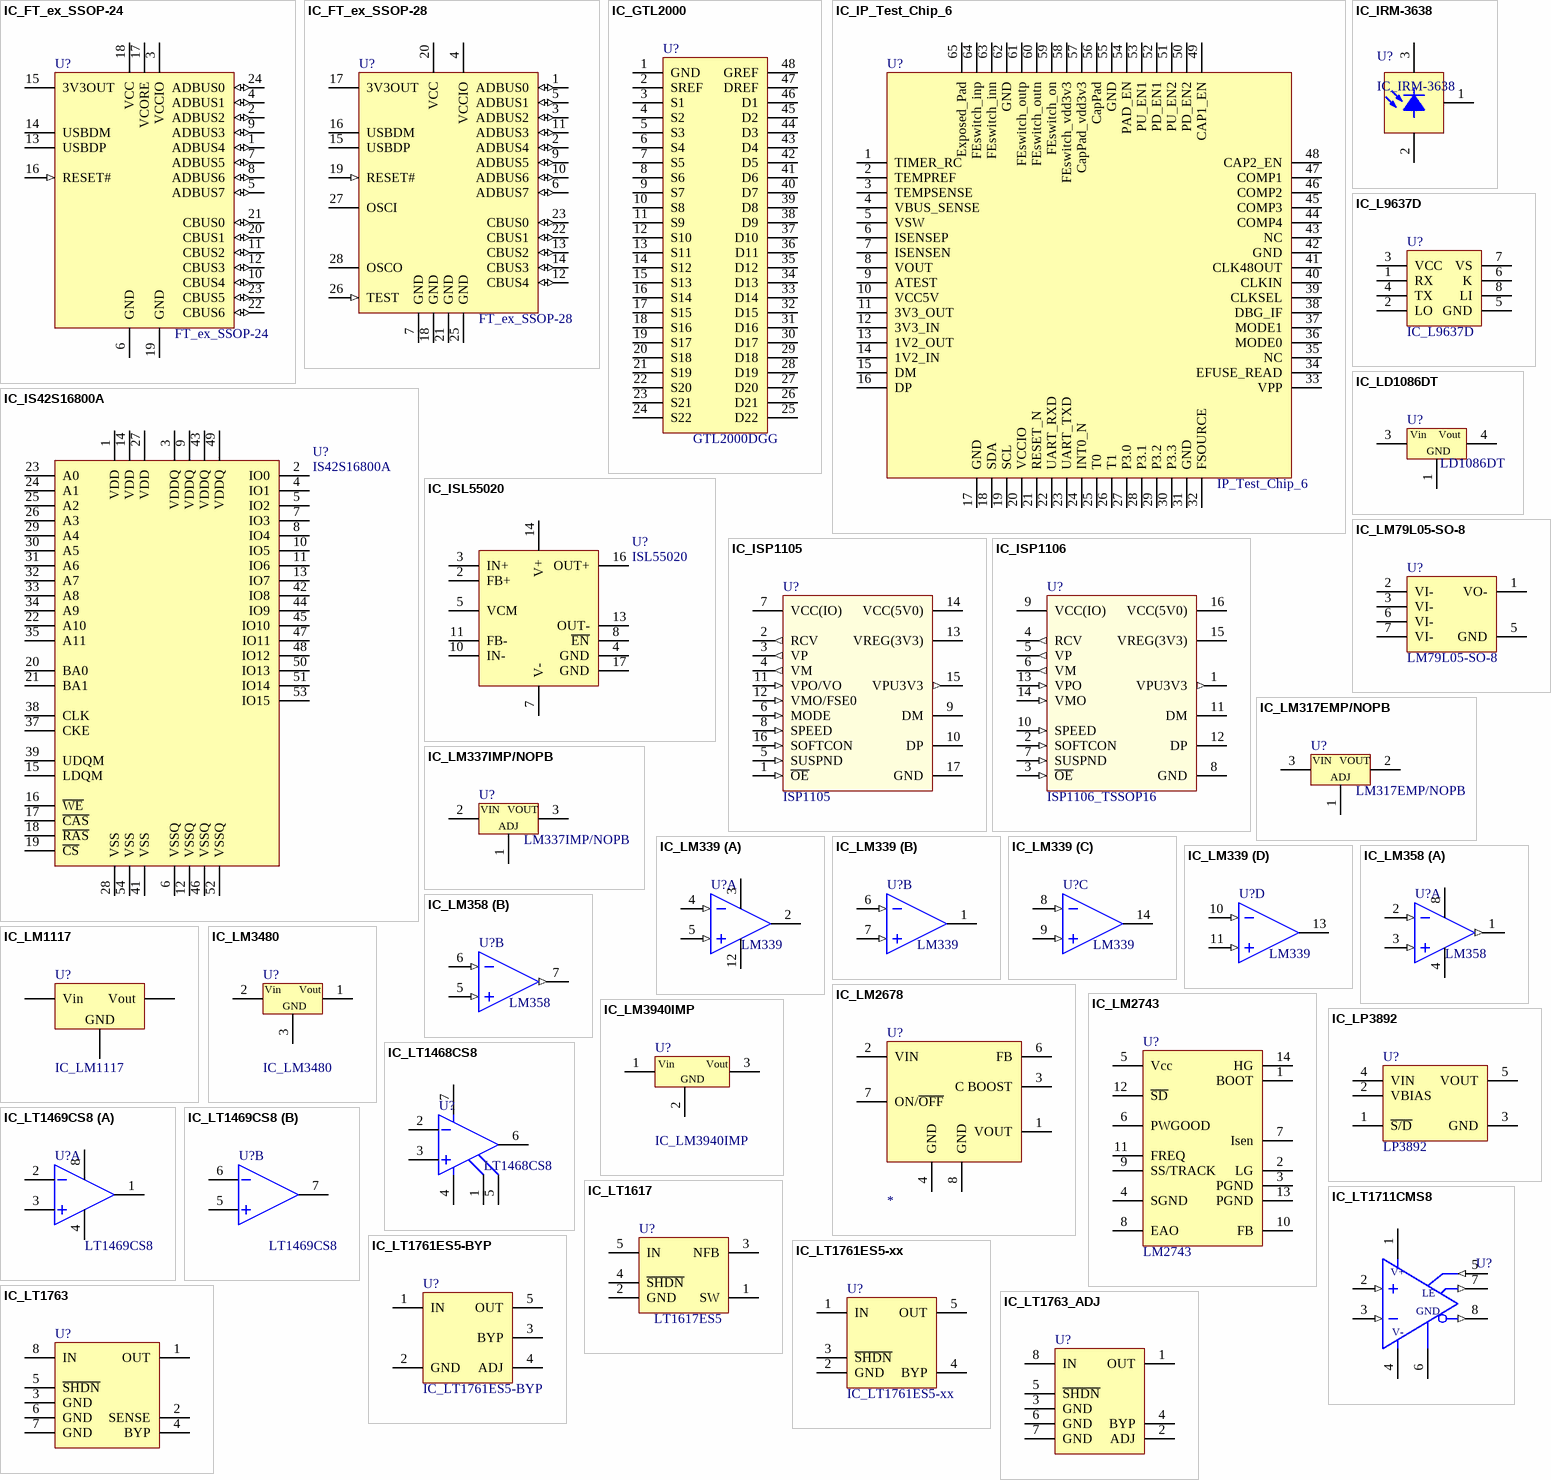
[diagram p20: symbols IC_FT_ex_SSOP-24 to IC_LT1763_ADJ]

## IC_FT_ex_SSOP-24
designator U?, comment FT_ex_SSOP-24
FT_ex-SSOP-24; Do not use on customer designs
footprint SSOP635P600X175-24N (SSOP, 24-Leads, Body 8.7x4.0mm (max), Pitch 0.635mm, IPC Medium Density)
pins: 1 ADBUS4 (io), 2 ADBUS2 (io), 3 VCCIO (power), 4 ADBUS1 (io), 5 ADBUS7 (io), 6 GND (power), 7 ADBUS5 (io), 8 ADBUS6 (io), 9 ADBUS3 (io), 10 CBUS4 (io), 11 CBUS2 (io), 12 CBUS3 (io), 13 USBDP, 14 USBDM, 15 3V3OUT (power), 16 RESET# (in), 17 VCORE (power), 18 VCC (power), 19 GND (power), 20 CBUS1 (io), 21 CBUS0 (io), 22 CBUS6 (io), 23 CBUS5 (io), 24 ADBUS0 (io)

## IC_FT_ex_SSOP-28
designator U?, comment FT_ex_SSOP-28
FT_ex-SSOP-28; Do not use on customer designs
footprint SSOP65P780X200-28N (SSOP, 28-Leads, Body 10.3x5.6mm (max), Pitch 0.65mm, IPC Medium Density)
pins: 1 ADBUS0 (io), 2 ADBUS4 (io), 3 ADBUS2 (io), 4 VCCIO (power), 5 ADBUS1 (io), 6 ADBUS7 (io), 7 GND (power), 8 NC hidden, 9 ADBUS5 (io), 10 ADBUS6 (io), 11 ADBUS3 (io), 12 CBUS4 (io), 13 CBUS2 (io), 14 CBUS3 (io), 15 USBDP, 16 USBDM, 17 3V3OUT (power), 18 GND (power), 19 RESET# (in), 20 VCC (power), 21 GND (power), 22 CBUS1 (io), 23 CBUS0 (io), 24 NC hidden, 25 GND (power), 26 TEST (in), 27 OSCI, 28 OSCO

## IC_GTL2000
designator U?, comment GTL2000DGG
22-bit Bidirectional Vlotage Translator
footprint TSSOP50P810X120-48N (TSSOP, 48-Leads, Body 12.6x6.2mm (max), Pitch 0.50mm, IPC Medium Density)
pins: 1 GND, 2 SREF, 3 S1, 4 S2, 5 S3, 6 S4, 7 S5, 8 S6, 9 S7, 10 S8, 11 S9, 12 S10, 13 S11, 14 S12, 15 S13, 16 S14, 17 S15, 18 S16, 19 S17, 20 S18, 21 S19, 22 S20, 23 S21, 24 S22, 25 D22, 26 D21, 27 D20, 28 D19, 29 D18, 30 D17, 31 D16, 32 D15, 33 D14, 34 D13, 35 D12, 36 D11, 37 D10, 38 D9, 39 D8, 40 D7, 41 D6, 42 D5, 43 D4, 44 D3, 45 D2, 46 D1, 47 DREF, 48 GREF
